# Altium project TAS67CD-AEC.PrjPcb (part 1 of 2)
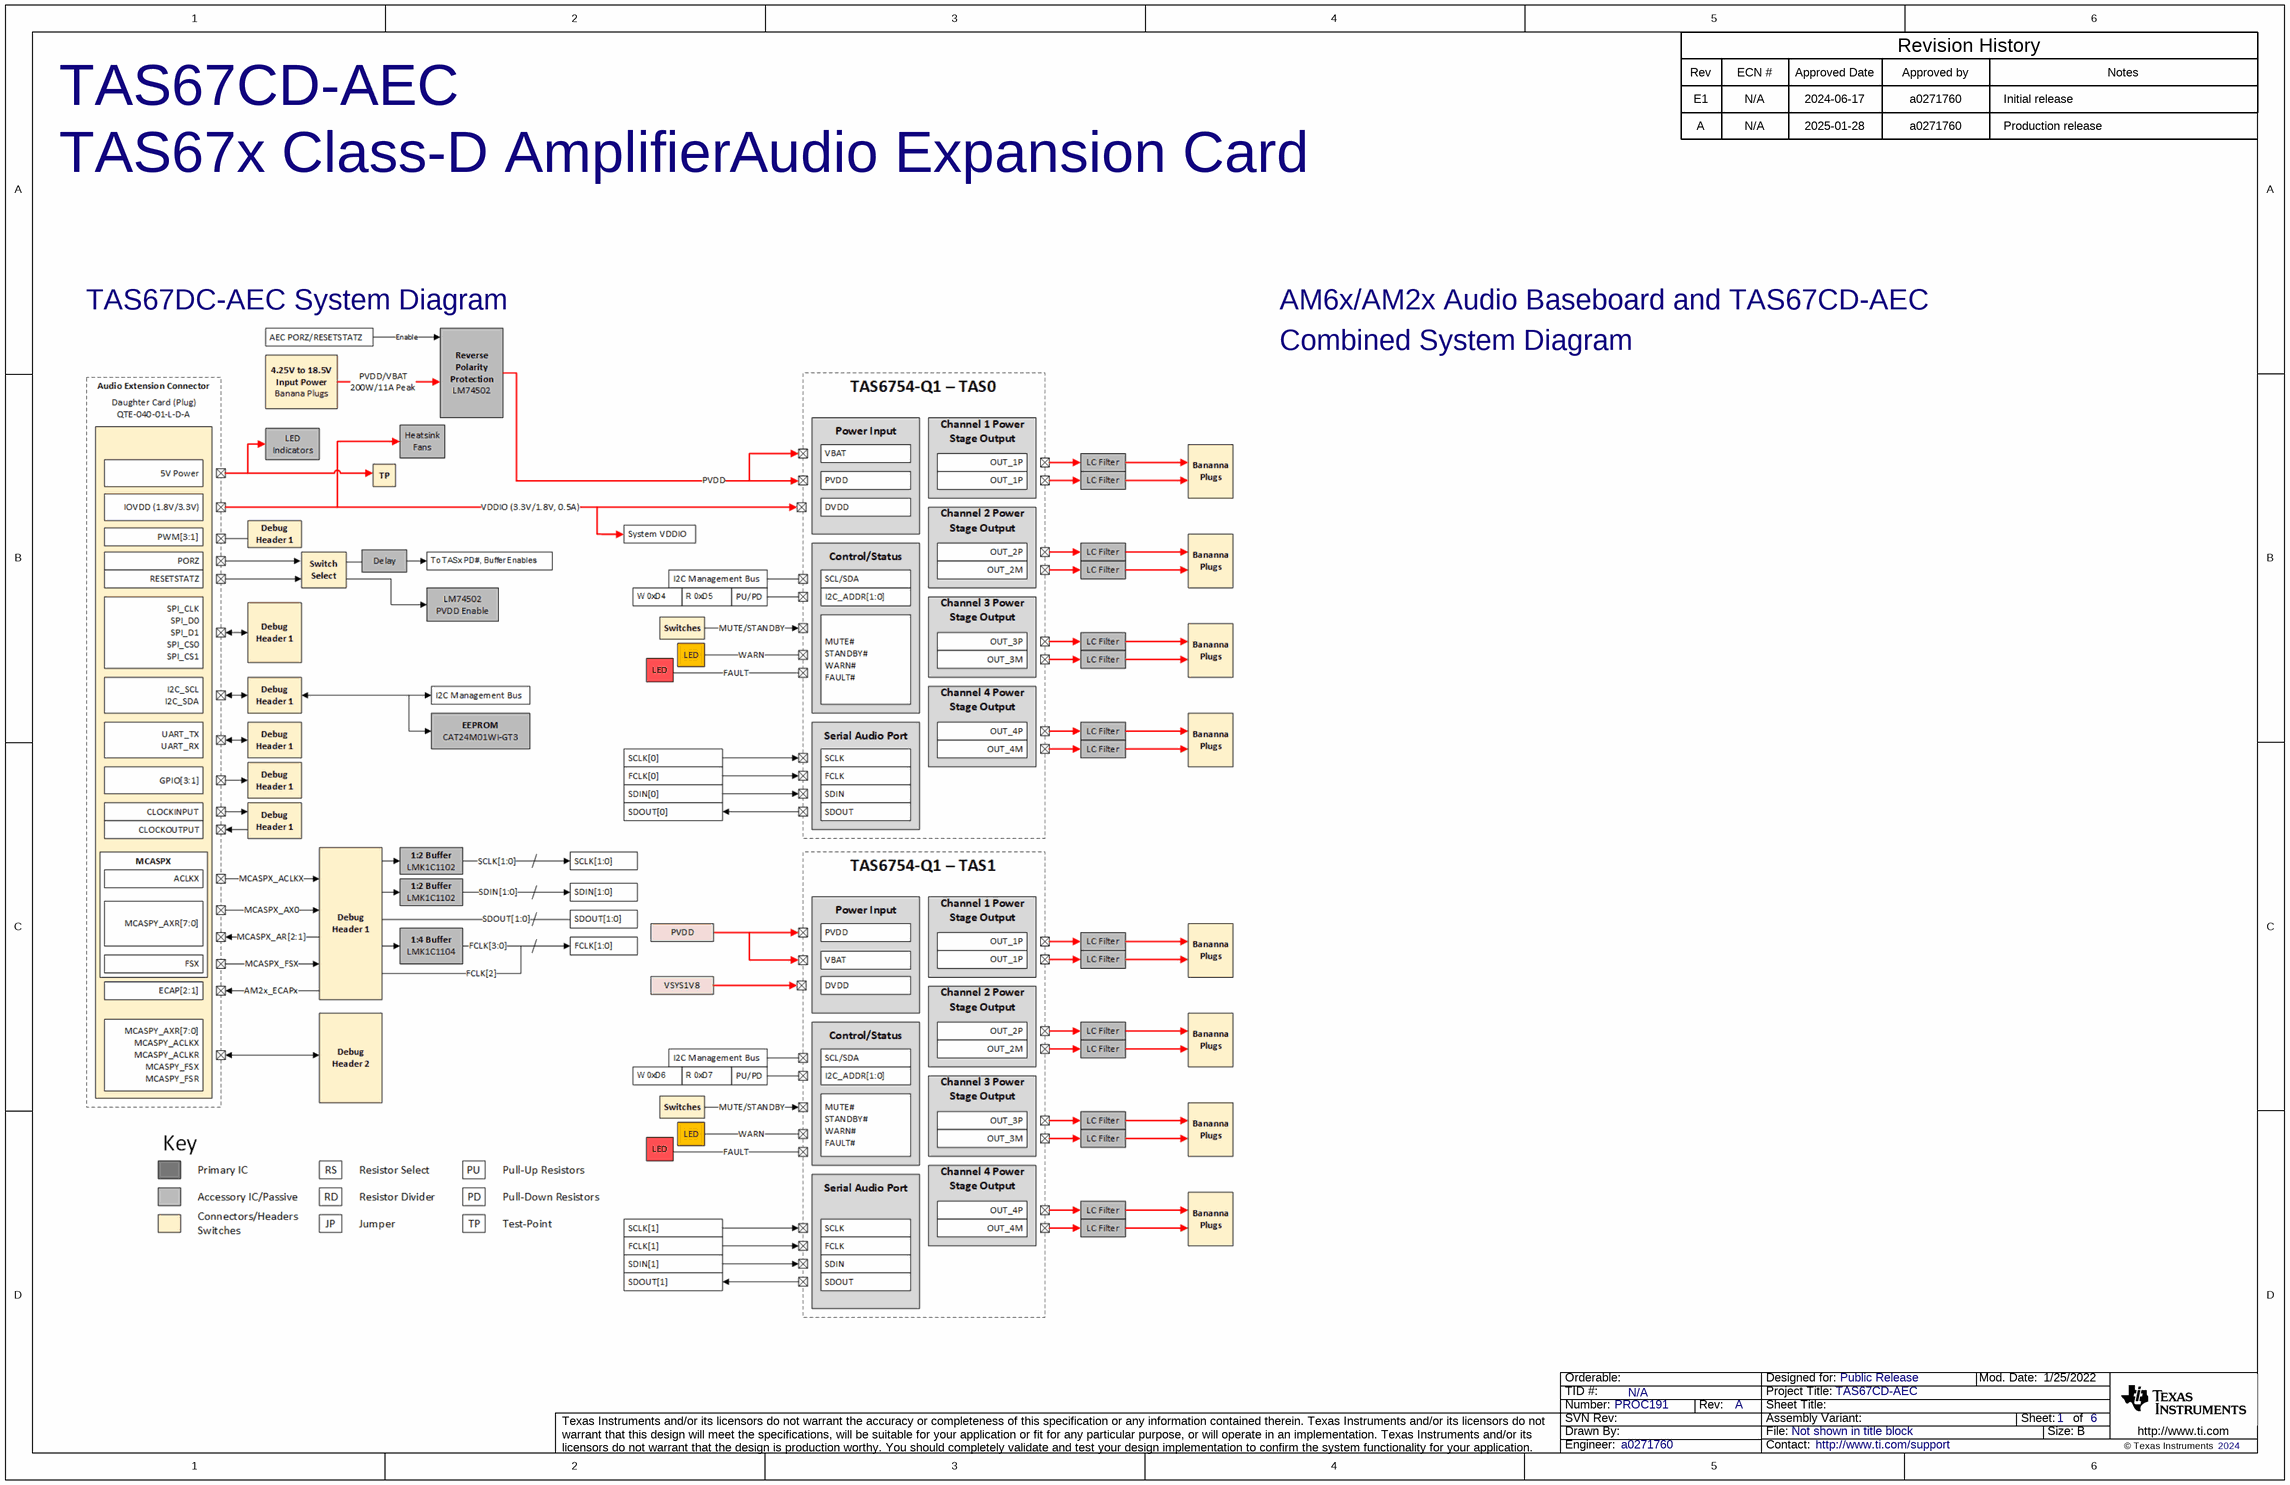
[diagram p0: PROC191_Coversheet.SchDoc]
CopyrightYear: 2024; PCB_Layout: a0271760; PCB_Rev: A; PRJ_Customer: Public Release; PRJ_Engineer: a0271760; PRJ_Number: PROC191; PRJ_Title: TAS67CD-AEC; SCH_Rev: A; TechSupport: http://www.ti.com/support; TID: N/A
6 sheets, 310 parts. Net scope: global (net labels, ports and power ports of the same name join across sheets).
Board file: PROC191A.PcbDoc
Sheets:
  PROC191_Coversheet.SchDoc
  PROC191_Power.SchDoc
  PROC191_ExpansionConnector.SchDoc
  PROC191_TAS0.SchDoc
  PROC191_TAS1.SchDoc
  PROC191_Hardware.SchDoc

## Sheet PROC191_Coversheet.SchDoc
size 431 x 279 mm; Date: Not shown in title block; ApprovedBy: Not shown in title block; CheckedBy: Not shown in title block; Author: Not shown in title block; CompanyName: Not shown in title block; Engineer: Not shown in title block; Organization: Not shown in title block; Address1: Not shown in title block; Address2: Not shown in title block; Address3: Not shown in title block; Address4: Not shown in title block; DocumentNumber: 1; Revision: Use project parameter SCH_Rev; SheetNumber: 1; SheetTotal: 6; PageSetup: Record=PageOptions¦CenterHorizontal=True¦CenterVertical=True¦PrintScale=1.00¦XCorrection=1.00¦YCorrection=1.00¦PrintKind=0¦BorderSize=5000000¦LeftOffset=0¦BottomOffset=0¦Orientation=2¦PaperLength=1000¦PaperWidth=1000¦Scale=100¦PaperSource=15¦PrintQuality=600¦MediaType=1¦DitherType=10¦PaperKind=Letter¦PrintScaleMode=1

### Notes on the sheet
- TAS67CD-AEC
- Rev
- E1
- ECN #
- N/A
- Approved Date
- 2024-06-17
- Approved by
- a0271760
- Revision History
- Initial release
- Notes
- TAS67x Class-D Amplifier
- Audio Expansion Card
- A
- 2025-01-28
- Production release
- TAS67DC-AEC System Diagram
- AM6x/AM2x Audio Baseboard and TAS67CD-AEC
- Combined System Diagram

## Sheet PROC191_Power.SchDoc
size 431 x 279 mm; Date: Not shown in title block; ApprovedBy: Not shown in title block; CheckedBy: Not shown in title block; Author: Not shown in title block; CompanyName: Not shown in title block; Engineer: Not shown in title block; Organization: Not shown in title block; Address1: Not shown in title block; Address2: Not shown in title block; Address3: Not shown in title block; Address4: Not shown in title block; DocumentNumber: 3; Revision: Use project parameter SCH_Rev; SheetNumber: 2; SheetTotal: 6; PageSetup: Record=PageOptions¦CenterHorizontal=True¦CenterVertical=True¦PrintScale=1.00¦XCorrection=1.00¦YCorrection=1.00¦PrintKind=0¦BorderSize=5000000¦LeftOffset=0¦BottomOffset=0¦Orientation=2¦PaperLength=1000¦PaperWidth=1000¦Scale=100¦PaperSource=15¦PrintQuality=600¦MediaType=1¦DitherType=10¦PaperKind=Letter¦PrintScaleMode=1
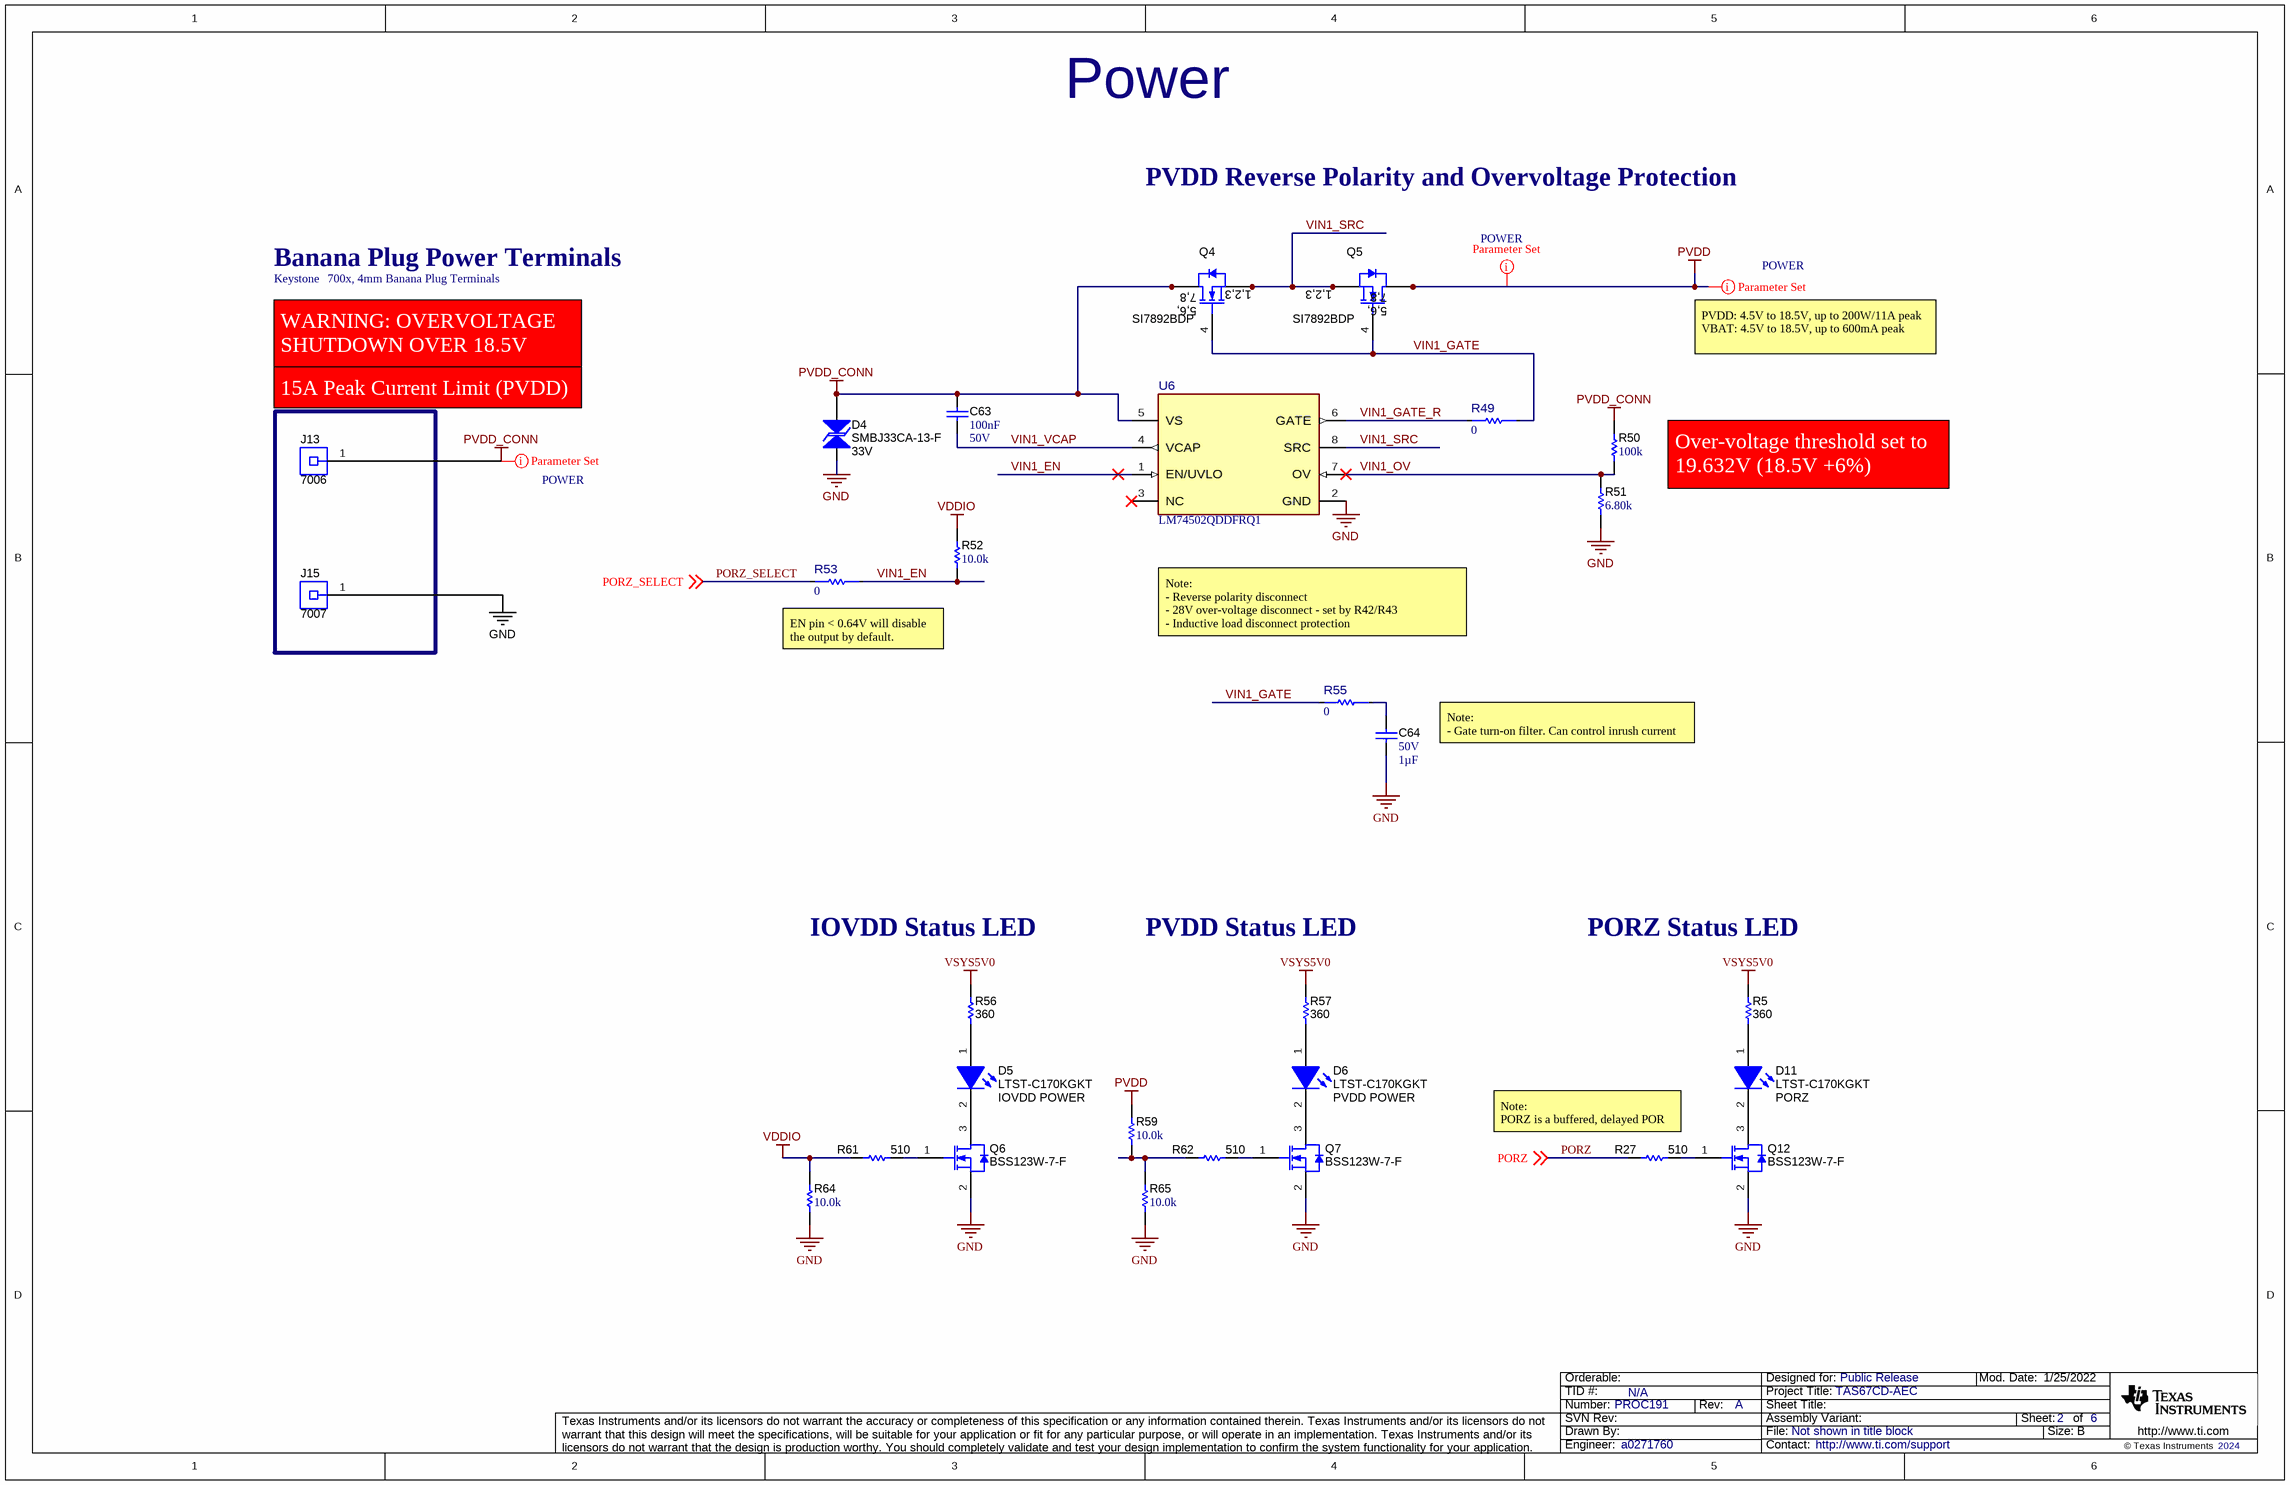
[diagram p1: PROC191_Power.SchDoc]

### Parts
C63  Cap_F: 100nF  VDC_V: 50V  [0603]  (hidden comment: GCM188R71H104KA57D)
C64  VDC_V: 50V  ValueDisplayed: 1µF  [0603]  (hidden comment: CGA3E3X5R1H105M080AB)
D4  SMBJ33CA-13-F  value 33V  [SMB-Bi]
D5  LTST-C170KGKT  value IOVDD POWER  [LTST-C170KGKT_Green]
D6  LTST-C170KGKT  value PVDD POWER  [LTST-C170KGKT_Green]
D11  LTST-C170KGKT  value PORZ  [LTST-C170KGKT_Green]
J13  7006  Manufacturer: Keystone  [Keystone_7006]
J15  7007  [Keystone_7007]
Q4  SI7892BDP  [PowerPAK_SO-8]
Q5  SI7892BDP  [PowerPAK_SO-8]
Q6  BSS123W-7-F  [SOT-323]
Q7  BSS123W-7-F  [SOT-323]
Q12  BSS123W-7-F  [SOT-323]
R5  ValueDisplayed: 360  [0402]  (hidden comment: ERJ-2GEJ361X)
R27  ValueDisplayed: 510  [0402]  (hidden comment: ERJ-2GEJ511X)
R49  Res_ohm: 0  [FP-ERJ-3GEY0R00V_0603-IPC_B]  (hidden comment: ERJ-3GEY0R00V)
R50  ValueDisplayed: 100k  [0603]  (hidden comment: RC0603FR-07100KL)
R51  ValueDisplayed: 6.80k  [0603]  (hidden comment: RC0603FR-076K8L)
R52  ValueDisplayed: 10.0k  [0603]  (hidden comment: RC0603FR-0710KL)
R53  Res_ohm: 0  [FP-ERJ-3GEY0R00V_0603-IPC_B]  (hidden comment: ERJ-3GEY0R00V)
R55  Res_ohm: 0  [FP-ERJ-3GEY0R00V_0603-IPC_B]  (hidden comment: ERJ-3GEY0R00V)
R56  ValueDisplayed: 360  [0402]  (hidden comment: ERJ-2GEJ361X)
R57  ValueDisplayed: 360  [0402]  (hidden comment: ERJ-2GEJ361X)
R59  ValueDisplayed: 10.0k  [0402]  (hidden comment: ERJ-2RKF1002X)
R61  ValueDisplayed: 510  [0402]  (hidden comment: ERJ-2GEJ511X)
R62  ValueDisplayed: 510  [0402]  (hidden comment: ERJ-2GEJ511X)
R64  ValueDisplayed: 10.0k  [0402]  (hidden comment: ERJ-2RKF1002X)
R65  ValueDisplayed: 10.0k  [0402]  (hidden comment: ERJ-2RKF1002X)
U6  PartNumber: LM74502QDDFRQ1  [DDF0008A-MFG]  (hidden comment: PartNumber)

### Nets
GND: C64.2 D4.1 J15.1 Q6.2(S) Q7.2(S) Q12.2(S) R51.1 R64.2 R65.2 U6.2(GND)
PVDD: Q5.5(D) Q5.6(D) Q5.7(D) Q5.8(D) Q5.9(D) R59.1
PVDD_CONN: C63.1 D4.2 J13.1 Q4.5(D) Q4.6(D) Q4.7(D) Q4.8(D) Q4.9(D) R50.2 U6.5(VS)
VDDIO: R52.2 R61.1 R64.1
VSYS5V0: R5.2 R56.2 R57.2
PORZ: R27.1 ; off-sheet PORZ
PORZ_SELECT: R53.2 ; off-sheet PORZ_SELECT
VIN1_EN: R52.1 R53.1 U6.1(EN/UVLO)
VIN1_GATE: Q4.4(G) Q5.4(G) R49.1 R55.2
VIN1_GATE_R: R49.2 U6.6(GATE)
VIN1_OV: R50.1 R51.2 U6.7(OV)
VIN1_SRC: Q4.1(S) Q4.2(S) Q4.3(S) Q5.1(S) Q5.2(S) Q5.3(S) U6.8(SRC)
VIN1_VCAP: C63.2 U6.4(VCAP)
NetC64_1: C64.1 R55.1
NetD5_1: D5.1(A) R56.1
NetD5_2: D5.2(K) Q6.3(D)
NetD6_1: D6.1(A) R57.1
NetD6_2: D6.2(K) Q7.3(D)
NetD11_1: D11.1(A) R5.1
NetD11_2: D11.2(K) Q12.3(D)
NetQ6_1: Q6.1(G) R61.2
NetQ7_1: Q7.1(G) R62.2
NetQ12_1: Q12.1(G) R27.2
NetR59_2: R59.2 R62.1 R65.1

Not connected (* = marked no-connect by the designer): U6 3(NC)*

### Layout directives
net class POWER: PVDD, PVDD_CONN

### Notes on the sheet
- Power
- PVDD Reverse Polarity and Overvoltage Protection
- Banana Plug Power Terminals
- 700x, 4mm Banana Plug Terminals
- WARNING: OVERVOLTAGE SHUTDOWN OVER 18.5V INPUT
- PVDD: 4.5V to 18.5V, up to 200W/11A peak
  VBAT: 4.5V to 18.5V, up to 600mA peak
- 15A Peak Current Limit (PVDD)
- Over-voltage threshold set to 19.632V (18.5V +6%)
- Note:
  - Reverse polarity disconnect
  - 28V over-voltage disconnect - set by R42/R43
  - Inductive load disconnect protection
- EN pin < 0.64V will disable the output by default.
- Note:
  - Gate turn-on filter. Can control inrush current
- IOVDD Status LED
- PVDD Status LED
- PORZ Status LED
- Note:
  PORZ is a buffered, delayed POR signal

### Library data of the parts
C63 = CMP-0007144-4: CAP, CERM, 0.1 uF, 50 V, +/- 10%, X7R, 0603; Manufacturer: MuRata; TaMin_C: -55°C; ESR_ohm: 20m; Polarized: N; SizeAreaWB_mm2: 4.68; Value1: 0.02 ohm; U/M: EA; Value: 0.1uF; TaMax_C: 125°C; SizeZ_mm: 1; SizeX_mm: 1.6; SizeY_mm: 0.8; SizeArea_mm2: 1.28; IRMS_A: 1.84A; AEC Category: Q200
C64 = CMP-0083707-1: CAP, CERM, 1 µF, 50 V,+/- 20%, X5R, AEC-Q200 Grade 3, 0603; Manufacturer: TDK; SizeAreaWB_mm2: 4.68; SizeArea_mm2: 1.28; AEC Qualified: Y; AEC Category: Q200; Value: 1uF; TaMax_C: 85°C; SizeZ_mm: 1; AEC Grade: 3; Polarized: N; TaMin_C: -55°C; SizeY_mm: 0.8; U/M: EA; SizeX_mm: 1.6
D4 = CMP-0005564-3: Diode, TVS, Bi, 33 V, SMB; Manufacturer: Diodes Inc.; SizeX_mm: 5.6; Ppk: 600W; SizeAreaWB_mm2: 44.156; SizeZ_mm: 2.6; SizeArea_mm2: 21.336; SizeY_mm: 3.81; AEC Category: Q101
D5 D6 D11 = CMP-0002888-2: LED, Green, SMD; Manufacturer: Lite-On; Value1: W; Vf_V: 2V; Type: AlInGaP; Io_A: 20mA
J13 = CMP-0055127-1: Binding Post, RED, TH; CNHeader: FALSE; Green_Lifecycle: Active; Green_REACh: Passed; CompType: Connector
J15 = CMP-0055128-1: Binding Post, BLACK, TH; Manufacturer: Keystone; CNHeader: FALSE; Green_Lifecycle: Active; Green_REACh: Passed; CompType: Connector
Q4 Q5 = CMP-0000665-1: MOSFET, N-CH, 30 V, 15 A, PowerPAK SO-8; Alternate Manufacturer: None; Manufacturer: Vishay-Siliconix; SizeZ_mm: 1.12; ChType: N; Value2: 27 nC; Value1: 0.005; VdsMax_V: 30V; SizeX_mm: 5.99; SizeAreaWB_mm2: 55.131; SizeY_mm: 4.9; Vgs_V: 20V; QgTyp_nC: 27; Value: 30V; Rdson45_ohm: 5.7m; SizeArea_mm2: 29.351; AEC Category: Q101; IdsMax_A: 15A; U/M: EA
Q6 Q7 Q12 = CMP-0000948-2: MOSFET, N-CH, 100 V, 0.17 A, SOT-323; Alternate Manufacturer: None; Manufacturer: Diodes Inc.; SizeZ_mm: 1.1; ChType: N; Value1: 1; VdsMax_V: 100V; SizeX_mm: 2.2; Vgs_V: 20V; Value: 100V; Rdson45_ohm: 10; SizeArea_mm2: 4.84; AEC Category: Q101; IdsMax_A: 170mA; SizeAreaWB_mm2: 10.24; U/M: EA
R5 R56 R57 = CMP-0078194-1: RES, 360, 5%, 0.1 W, AEC-Q200 Grade 0, 0402; Manufacturer: Panasonic; Value_Code: 360R; SizeArea_mm2: 0.5; AEC Qualified: Y; AEC Category: Q200; Value: 360; SizeZ_mm: 0.6; EIA_Code: E24; TempCo: 200 ppm/C; AEC Grade: 0; Power_W: 100mW; VDC_V: 50V; Value2: 0.1W; U/M: EA; SizeX_mm: 1
R27 R61 R62 = CMP-0078212-1: RES, 510, 5%, 0.1 W, AEC-Q200 Grade 0, 0402; Manufacturer: Panasonic; Value_Code: 510R; SizeArea_mm2: 0.5; AEC Qualified: Y; AEC Category: Q200; Value: 510; SizeZ_mm: 0.6; EIA_Code: E24; TempCo: 200 ppm/C; AEC Grade: 0; Power_W: 100mW; VDC_V: 50V; Value2: 0.1W; U/M: EA; SizeX_mm: 1
R49 R53 R55 = CMP-0089143-1: 0 Ohms Jumper 0.1W, 1/10W Chip Resistor 0603 (1608 Metric) Automotive AEC-Q200 Thick Film; Manufacturer: Panasonic; SizeZ_mm: 0.55mm; AEC Grade: Grade 0; VDC_V: 75V; TempCo: -100/+600ppm/°C; AEC Qualified: Yes; Power_W: 100mW; Tolerance_%: 5%
R50 = CMP-0022735-5: RES, 100 k, 1%, 0.1 W, 0603; Manufacturer: Yageo; Power_W: 100mW; TempCo: 100 ppm/C; Value: 100k; EIA_Code: E96; SizeX_mm: 1.6; SizeY_mm: 0.8; SizeZ_mm: 1; Value2: 0.1W; SizeArea_mm2: 1.28; AEC Qualified: N; VDC_V: 75V; AEC Category: Q200; SizeAreaWB_mm2: 4.68
R51 = CMP-0023253-5: RES, 6.80 k, 1%, 0.1 W, 0603; Manufacturer: Yageo; Power_W: 100mW; TempCo: 100 ppm/C; Value_Code: 6k80; Value: 6.80k; Res_ohm: 6.8k; SizeX_mm: 1.6; SizeY_mm: 0.8; SizeZ_mm: 1; Value2: 0.1W; SizeArea_mm2: 1.28; AEC Qualified: N; VDC_V: 75V; AEC Category: Q200; SizeAreaWB_mm2: 4.68
R52 = CMP-0022746-5: RES, 10.0 k, 1%, 0.1 W, 0603; Manufacturer: Yageo; Power_W: 100mW; TempCo: 100 ppm/C; Value_Code: 10k0; Value: 10.0k; EIA_Code: E96; Res_ohm: 10k; SizeX_mm: 1.6; SizeY_mm: 0.8; SizeZ_mm: 1; Value2: 0.1W; SizeArea_mm2: 1.28; AEC Qualified: N; VDC_V: 75V; AEC Category: Q200; SizeAreaWB_mm2: 4.68
R59 R64 R65 = CMP-0026658-1: RES, 10.0 k, 1%, 0.1 W, 0402; Manufacturer: Panasonic; Power_W: 100mW; TempCo: 100 ppm/C; Value_Code: 10k0; U/M: EA; Value: 10.0k; EIA_Code: E96; Res_ohm: 10k; SizeX_mm: 1; SizeY_mm: 0.5; SizeZ_mm: 0.6; Value2: 0.1W; VDC_V: 50V; AEC Category: Q200
U6 = CMP-0095578-1: Low IQ High Side Switch Controller With Reverse Polarity and Overvoltage Protection; Manufacturer: Texas Instruments; TJmax_C: +150°C; AEC Qualified: No; SizeZ_mm: 1.1mm; Nominal Supply Current: 45uA; Min Supply Voltage: 4V; Number Of Outputs: 1; Standoff Height: 0mm; Max Supply Voltage: 60V; TaMax_C: +125°C; TaMin_C: -40°C

## Sheet PROC191_ExpansionConnector.SchDoc
size 431 x 279 mm; Date: Not shown in title block; ApprovedBy: Not shown in title block; CheckedBy: Not shown in title block; Author: Not shown in title block; CompanyName: Not shown in title block; Engineer: Not shown in title block; Organization: Not shown in title block; Address1: Not shown in title block; Address2: Not shown in title block; Address3: Not shown in title block; Address4: Not shown in title block; DocumentNumber: 2; Revision: Use project parameter SCH_Rev; SheetNumber: 3; SheetTotal: 6; PageSetup: Record=PageOptions¦CenterHorizontal=True¦CenterVertical=True¦PrintScale=1.00¦XCorrection=1.00¦YCorrection=1.00¦PrintKind=0¦BorderSize=5000000¦LeftOffset=0¦BottomOffset=0¦Orientation=2¦PaperLength=1000¦PaperWidth=1000¦Scale=100¦PaperSource=15¦PrintQuality=600¦MediaType=1¦DitherType=10¦PaperKind=Letter¦PrintScaleMode=1
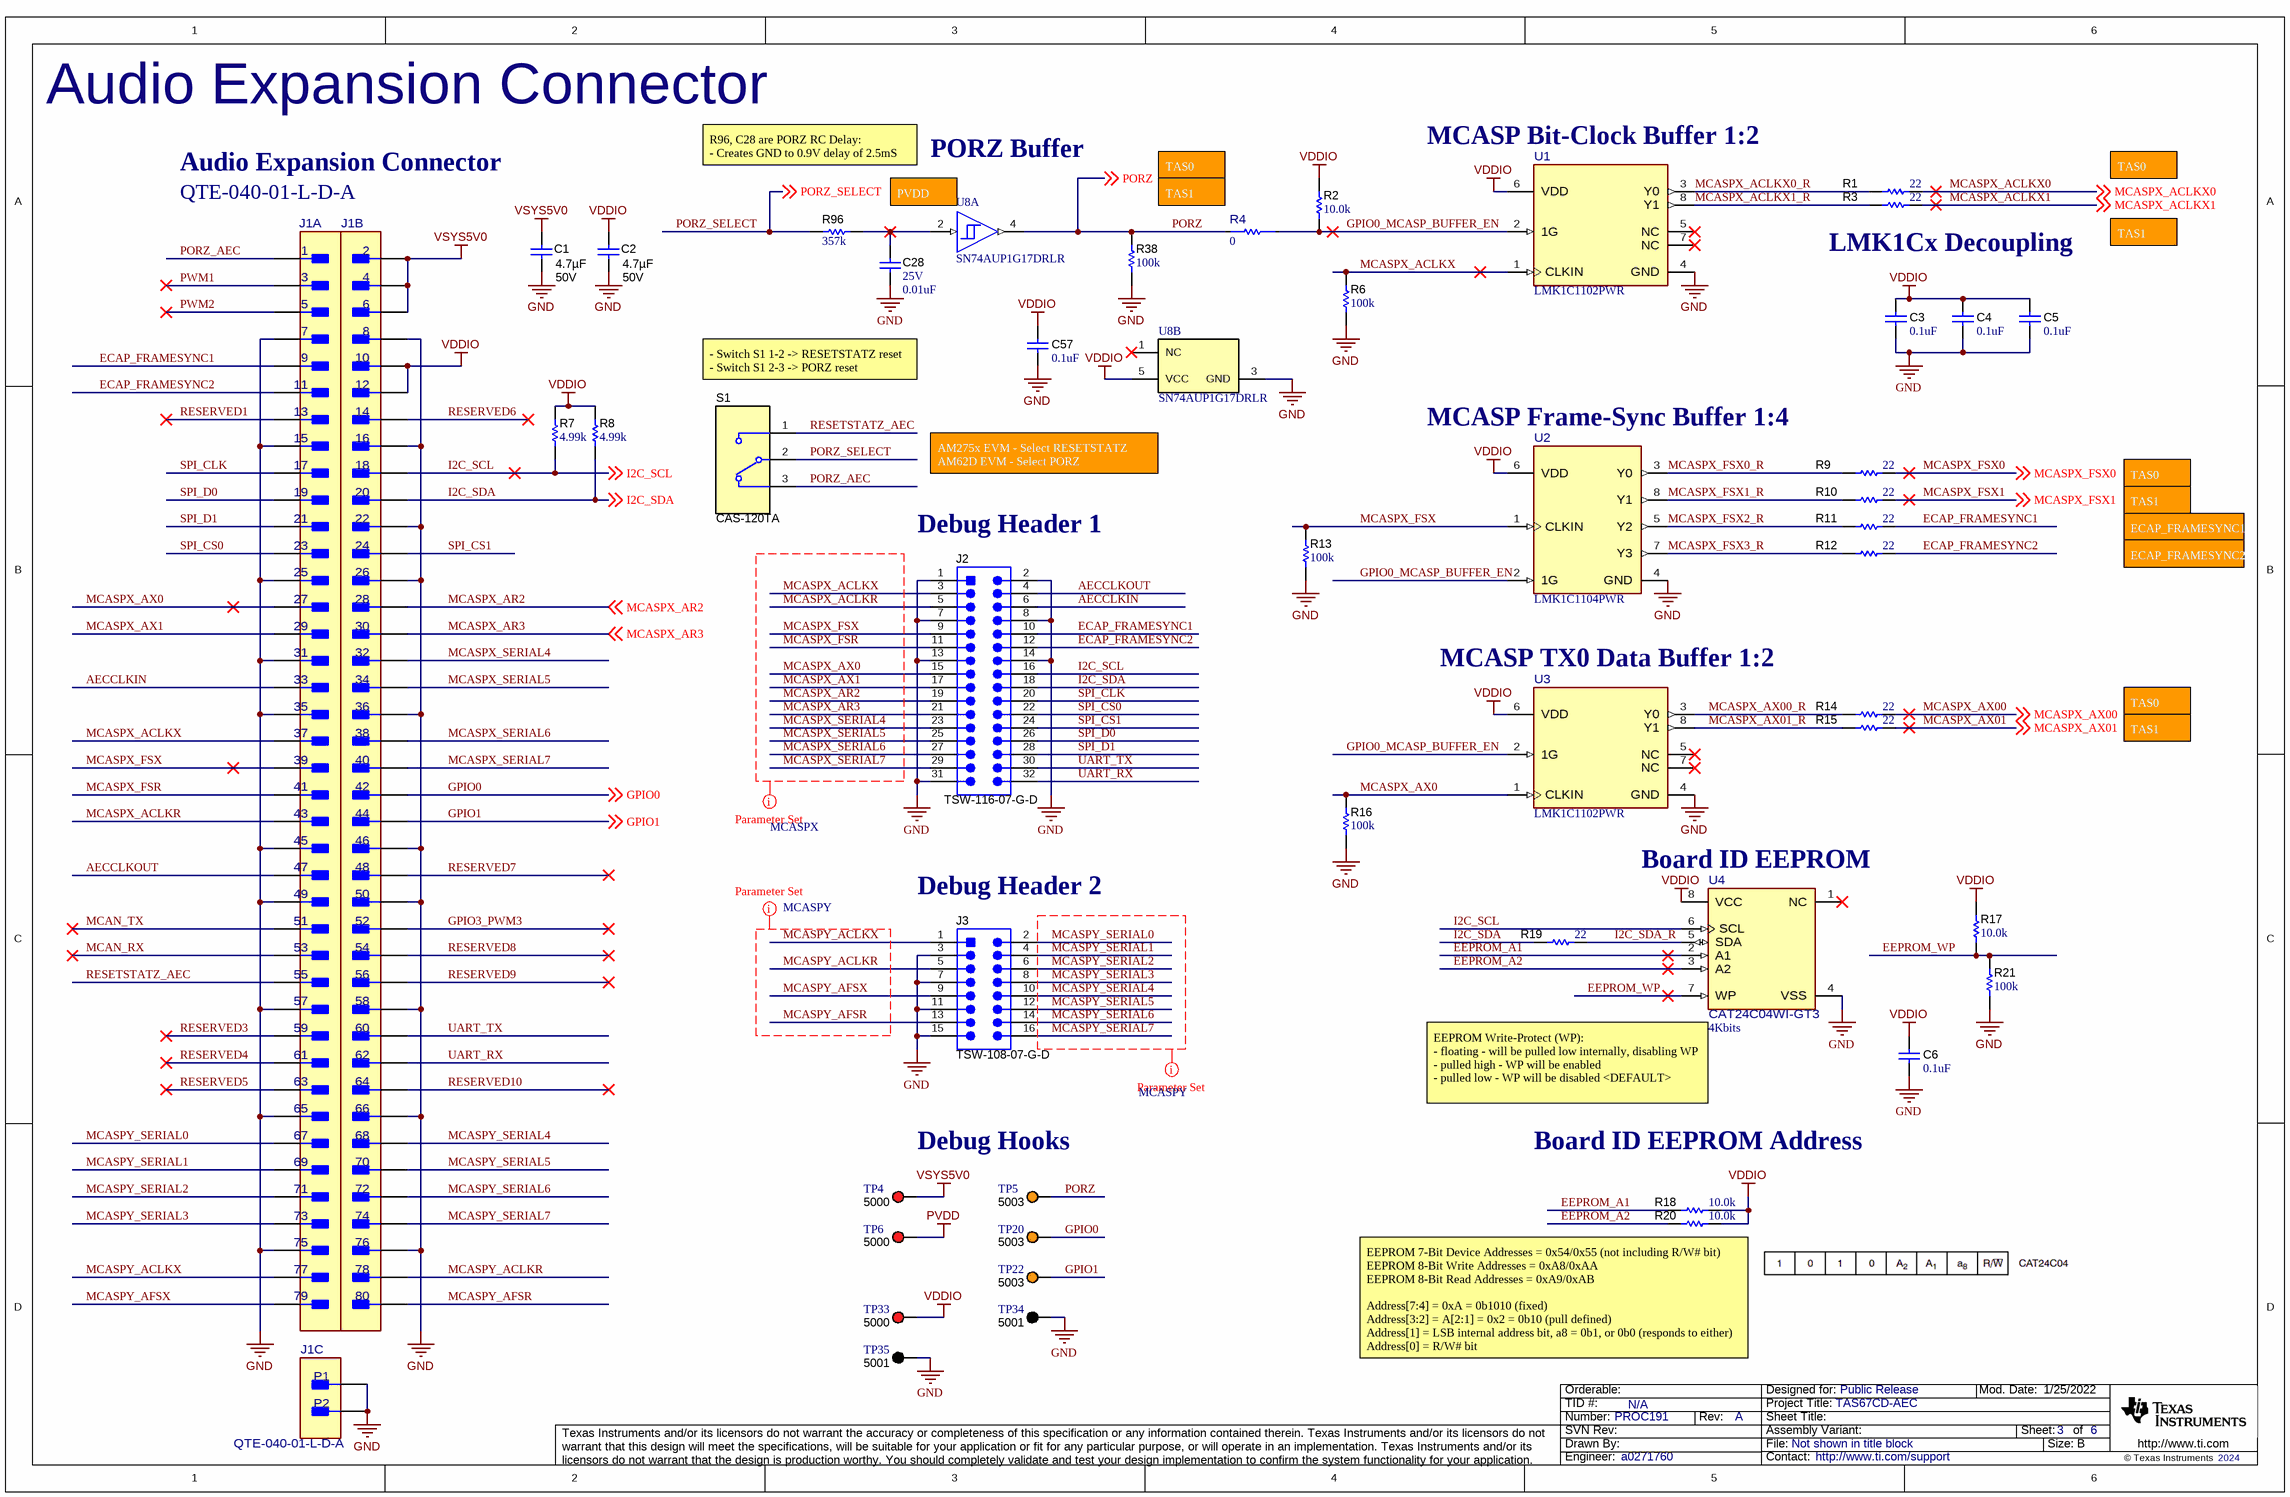
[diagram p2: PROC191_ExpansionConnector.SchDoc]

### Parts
C1  VDC_V: 50V  ValueDisplayed: 4.7µF  [1210_280]  (hidden comment: C1210C475K5RACAUTO)
C2  VDC_V: 50V  ValueDisplayed: 4.7µF  [1210_280]  (hidden comment: C1210C475K5RACAUTO)
C3  ValueDisplayed: 0.1uF  [0402]  (hidden comment: GRM155R71E104KE14D)
C4  ValueDisplayed: 0.1uF  [0402]  (hidden comment: GRM155R71E104KE14D)
C5  ValueDisplayed: 0.1uF  [0402]  (hidden comment: GRM155R71E104KE14D)
C6  ValueDisplayed: 0.1uF  [0402]  (hidden comment: GRM155R71E104KE14D)
C28  VDC_V: 25V  ValueDisplayed: 0.01uF  [0402]  (hidden comment: GRM155R71E103KA01D)
C57  ValueDisplayed: 0.1uF  [0402]  (hidden comment: GRM155R71E104KE14D)
J1  QTE-040-01-L-D-A  [FP-QTE-040-01-L-D-A_HDR80-MFG]  (parts A,B,C of 3)
J2  TSW-116-07-G-D  [TSW-116-07-G-D]
J3  TSW-108-07-G-D  [TSW-108-07-G-D]
R1  ValueDisplayed: 22  [0402]  (hidden comment: ERJ-2GEJ220X)
R2  ValueDisplayed: 10.0k  [0603]  (hidden comment: RC0603FR-0710KL)
R3  ValueDisplayed: 22  [0402]  (hidden comment: ERJ-2GEJ220X)
R4  Res_ohm: 0  [FP-ERJ-3GEY0R00V_0603-IPC_B]  (hidden comment: ERJ-3GEY0R00V)
R6  ValueDisplayed: 100k  [0603]  (hidden comment: RC0603FR-07100KL)
R7  ValueDisplayed: 4.99k  [0603]  (hidden comment: RC0603FR-074K99L)
R8  ValueDisplayed: 4.99k  [0603]  (hidden comment: RC0603FR-074K99L)
R9  ValueDisplayed: 22  [0402]  (hidden comment: ERJ-2GEJ220X)
R10  ValueDisplayed: 22  [0402]  (hidden comment: ERJ-2GEJ220X)
R11  ValueDisplayed: 22  [0402]  (hidden comment: ERJ-2GEJ220X)
R12  ValueDisplayed: 22  [0402]  (hidden comment: ERJ-2GEJ220X)
R13  ValueDisplayed: 100k  [0603]  (hidden comment: RC0603FR-07100KL)
R14  ValueDisplayed: 22  [0402]  (hidden comment: ERJ-2GEJ220X)
R15  ValueDisplayed: 22  [0402]  (hidden comment: ERJ-2GEJ220X)
R16  ValueDisplayed: 100k  [0603]  (hidden comment: RC0603FR-07100KL)
R17  ValueDisplayed: 10.0k  [0603]  (hidden comment: RC0603FR-0710KL)
R18  ValueDisplayed: 10.0k  [0603]  (hidden comment: RC0603FR-0710KL)
R19  ValueDisplayed: 22  [0402]  (hidden comment: ERJ-2GEJ220X)
R20  ValueDisplayed: 10.0k  [0603]  (hidden comment: RC0603FR-0710KL)
R21  ValueDisplayed: 100k  [0603]  (hidden comment: RC0603FR-07100KL)
R38  ValueDisplayed: 100k  [0603]  (hidden comment: RC0603FR-07100KL)
R96  ValueDisplayed: 357k  [0603]  (hidden comment: RC0603FR-07357KL)
S1  CAS-120TA  [SW_CAS-120TA]
TP4  5000  [Keystone5000]
TP5  5003  [Keystone5003]
TP6  5000  [Keystone5000]
TP20  5003  [Keystone5003]
TP22  5003  [Keystone5003]
TP33  5000  [Keystone5000]
TP34  5001  [Keystone5001]
TP35  5001  [Keystone5001]
U1  LMK1C1102PWR  [PW0008A-MFG]
U2  LMK1C1104PWR  [PW0008A-MFG]
U3  LMK1C1102PWR  [PW0008A-MFG]
U4  CAT24C04WI-GT3  Memory Size: 4Kbits  [FP-CAT24C04WI-GT3_SOIC8-IPC_C]
U8  SN74AUP1G17DRLR  [DRL0005A]  (parts A,B of 2)

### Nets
GND: C1.1 C2.1 C3.1 C4.1 C5.1 C6.1 C28.2 C57.1 J1.7 J1.8 J1.15 J1.16 J1.22 J1.25 J1.26 J1.31 J1.35 J1.36 J1.45 J1.46 J1.49 J1.50 J1.57 J1.58 J1.65 J1.66 J1.75 J1.76 J1.P1 J1.P2 J2.1 J2.2 J2.7 J2.8 J2.13 J2.14 J2.31 J3.3 J3.7 J3.11 J3.15 R6.1 R13.1 R16.1 R21.1 R38.1 TP34.1 TP35.1 U1.4(GND) U2.4(GND) U3.4(GND) U4.4(VSS) U8.3(GND)
PVDD: TP6.1
VDDIO: C2.2 C3.2 C4.2 C5.2 C6.2 C57.2 J1.10 J1.12 R2.1 R7.2 R8.2 R17.1 R18.1 R20.1 TP33.1 U1.6(VDD) U2.6(VDD) U3.6(VDD) U4.8(VCC) U8.5(VCC)
VSYS5V0: C1.2 J1.2 J1.4 J1.6 TP4.1
AECCLKIN: J1.33 J2.6
AECCLKOUT: J1.47 J2.4
ECAP_FRAMESYNC1: J1.9 J2.10 R11.2
ECAP_FRAMESYNC2: J1.11 J2.12 R12.2
EEPROM_A1: R18.2 U4.2(A1)
EEPROM_A2: R20.2 U4.3(A2)
EEPROM_WP: R17.2 R21.2 U4.7(WP)
GPIO0: J1.42 TP20.1 ; off-sheet GPIO0
GPIO0_MCASP_BUFFER_EN: R2.2 R4.1 U1.2(1G) U2.2(1G) U3.2(1G)
GPIO1: J1.44 TP22.1 ; off-sheet GPIO1
GPIO3_PWM3: J1.52
I2C_SCL: J1.18 J2.16 R7.1 U4.6(SCL) ; off-sheet I2C_SCL
I2C_SDA: J1.20 J2.18 R8.1 R19.1 ; off-sheet I2C_SDA
I2C_SDA_R: R19.2 U4.5(SDA)
MCAN_RX: J1.53
MCAN_TX: J1.51
MCASPX_ACLKR: J1.43 J2.5
MCASPX_ACLKX: J1.37 J2.3 R6.2 U1.1(CLKIN)
MCASPX_ACLKX0: R1.2 ; off-sheet MCASPX_ACLKX0
MCASPX_ACLKX0_R: R1.1 U1.3(Y0)
MCASPX_ACLKX1: R3.2 ; off-sheet MCASPX_ACLKX1
MCASPX_ACLKX1_R: R3.1 U1.8(Y1)
MCASPX_AR2: J1.28 J2.19 ; off-sheet MCASPX_AR2
MCASPX_AR3: J1.30 J2.21 ; off-sheet MCASPX_AR3
MCASPX_AX0: J1.27 J2.15 R16.2 U3.1(CLKIN)
MCASPX_AX00: R14.2 ; off-sheet MCASPX_AX00
MCASPX_AX00_R: R14.1 U3.3(Y0)
MCASPX_AX1: J1.29 J2.17
MCASPX_AX01: R15.2 ; off-sheet MCASPX_AX01
MCASPX_AX01_R: R15.1 U3.8(Y1)
MCASPX_FSR: J1.41 J2.11
MCASPX_FSX: J1.39 J2.9 R13.2 U2.1(CLKIN)
MCASPX_FSX0: R9.2 ; off-sheet MCASPX_FSX0
MCASPX_FSX0_R: R9.1 U2.3(Y0)
MCASPX_FSX1: R10.2 ; off-sheet MCASPX_FSX1
MCASPX_FSX1_R: R10.1 U2.8(Y1)
MCASPX_FSX2_R: R11.1 U2.5(Y2)
MCASPX_FSX3_R: R12.1 U2.7(Y3)
MCASPX_SERIAL4: J1.32 J2.23
MCASPX_SERIAL5: J1.34 J2.25
MCASPX_SERIAL6: J1.38 J2.27
MCASPX_SERIAL7: J1.40 J2.29
MCASPY_ACLKR: J1.78 J3.5
MCASPY_ACLKX: J1.77 J3.1
MCASPY_AFSR: J1.80 J3.13
MCASPY_AFSX: J1.79 J3.9
MCASPY_SERIAL0: J1.67 J3.2
MCASPY_SERIAL1: J1.69 J3.4
MCASPY_SERIAL2: J1.71 J3.6
MCASPY_SERIAL3: J1.73 J3.8
MCASPY_SERIAL4: J1.68 J3.10
MCASPY_SERIAL5: J1.70 J3.12
MCASPY_SERIAL6: J1.72 J3.14
MCASPY_SERIAL7: J1.74 J3.16
PORZ: R4.2 R38.2 TP5.1 U8.4(Y) ; off-sheet PORZ
PORZ_AEC: J1.1 S1.3
PORZ_SELECT: R96.1 S1.2 ; off-sheet PORZ_SELECT
PWM1: J1.3
PWM2: J1.5
RESERVED1: J1.13
RESERVED3: J1.59
RESERVED4: J1.61
RESERVED5: J1.63
RESERVED6: J1.14
RESERVED7: J1.48
RESERVED8: J1.54
RESERVED9: J1.56
RESERVED10: J1.64
RESETSTATZ_AEC: J1.55 S1.1
SPI_CLK: J1.17 J2.20
SPI_CS0: J1.23 J2.22
SPI_CS1: J1.24 J2.24
SPI_D0: J1.19 J2.26
SPI_D1: J1.21 J2.28
UART_RX: J1.62 J2.32
UART_TX: J1.60 J2.30
NetC28_1: C28.1 R96.2 U8.2(A)

Not connected (* = marked no-connect by the designer): U1 5(NC)* 7(NC)*; U3 5(NC)* 7(NC)*; U4 1(NC)*; U8 1(NC)*

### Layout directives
net class MCASPX: MCASPX_ACLKR, MCASPX_ACLKX, MCASPX_AR2, MCASPX_AR3, MCASPX_AX0, MCASPX_AX1, MCASPX_FSR, MCASPX_FSX, MCASPX_SERIAL4, MCASPX_SERIAL5, MCASPX_SERIAL6, MCASPX_SERIAL7
net class MCASPY: MCASPY_ACLKR, MCASPY_ACLKX, MCASPY_AFSR, MCASPY_AFSX, MCASPY_SERIAL0, MCASPY_SERIAL1, MCASPY_SERIAL2, MCASPY_SERIAL3, MCASPY_SERIAL4, MCASPY_SERIAL5, MCASPY_SERIAL6, MCASPY_SERIAL7

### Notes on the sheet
- Audio Expansion Connector
- R96, C28 are PORZ RC Delay:
  - Creates GND to 0.9V delay of 2.5mS
- PORZ Buffer
- TAS0
- (near U1) MCASP Bit-Clock Buffer 1:2
- (near U8) PVDD
- (near R4) TAS1
- TAS1
- LMK1Cx Decoupling
- - Switch S1 1-2 -> RESETSTATZ reset
  - Switch S1 2-3 -> PORZ reset
- (near U2) MCASP Frame-Sync Buffer 1:4
- AM275x EVM - Select RESETSTATZ
  AM62D EVM - Select PORZ
- (near J2) Debug Header 1
- ECAP_FRAMESYNC1
- ECAP_FRAMESYNC2
- MCASP TX0 Data Buffer 1:2
- (near J3) Debug Header 2
- (near U4) Board ID EEPROM
- (near U4) EEPROM Write-Protect (WP):
  - floating - will be pulled low internally, disabling WP
  - pulled high - WP will be enabled
  - pulled low - WP will be disabled <DEFAULT>
- Debug Hooks
- Board ID EEPROM Address
- (near R20) EEPROM 7-Bit Device Addresses = 0x54/0x55 (not including R/W# bit)
  EEPROM 8-Bit Write Addresses = 0xA8/0xAA
  EEPROM 8-Bit Read Addresses = 0xA9/0xAB
  Address[7:4] = 0xA = 0b1010 (fixed)
  Address[3:2] = A[2:1] = 0x2 = 0b10 (pull defined)
  Address[1] = LSB internal address bit, a8 = 0b1, or 0b0 (responds to either)
  Address[0] = R/W# bit

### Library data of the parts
C1 C2 = CMP-0079604-1: CAP, CERM, 4.7 µF, 50 V,+/- 10%, X7R, AEC-Q200 Grade 1, 1210; Manufacturer: Kemet; TaMin_C: -55°C; Polarized: N; SizeAreaWB_mm2: 14.7; U/M: EA; Value: 4.7uF; TaMax_C: 125°C; SizeZ_mm: 2.8; SizeX_mm: 3.2; SizeY_mm: 2.5; Cap_Case: 1210; SizeArea_mm2: 8; AEC Qualified: Y; AEC Grade: 1; AEC Category: Q200
C3-C6 C57 = CMP-0006659-2: CAP, CERM, 0.1 uF, 25 V, +/- 10%, X7R, 0402; Manufacturer: MuRata; TaMin_C: -55°C; Polarized: N; SizeAreaWB_mm2: 3; U/M: EA; Value: 0.1uF; TaMax_C: 125°C; SizeZ_mm: 0.6; SizeX_mm: 1; SizeY_mm: 0.5; Value2: 25V; Cap_F: 100nF; AEC Category: Q200; Value1: Unknown
C28 = CMP-0006658-2: CAP, CERM, 0.01 uF, 25 V, +/- 10%, X7R, 0402; Manufacturer: MuRata; TaMin_C: -55°C; Polarized: N; SizeAreaWB_mm2: 3; U/M: EA; Value: 0.01uF; TaMax_C: 125°C; SizeZ_mm: 0.6; SizeX_mm: 1; SizeY_mm: 0.5; Cap_F: 10nF; AEC Category: Q200; Value1: Unknown
J1 = CMP-0091968-1: 80 Position Connector Header, Outer Shroud Contacts Surface Mount Gold; Manufacturer: Samtec; SizeZ_mm: 4.347mm; AEC Qualified: No; Conn Gender: Male; Voltage_V: 225V; Row_Count: 2; ContactFinish: Gold,Nickel; Is Female: yes; Conn Orientation: Vertical; DUT-Pitch_mm: 0.8mm
J2 = CMP-0075429-1: Header, 100mil, 16x2, Gold, TH; Manufacturer: Samtec; Pitch_mm: 2.54; Cert_VDE: N; Gender: Male; Cert_CSA: Y; Voltage_V: 550V; Green_REACh: Passed; Current_A: 6.3A; CT: False; Green_Lifecycle: Active; Row_Count: 2; CNHeader: True
J3 = CMP-0075418-1: Header, 100mil, 8x2, Gold, TH; Manufacturer: Samtec; Pitch_mm: 2.54; Cert_VDE: N; Gender: Male; Cert_CSA: Y; Voltage_V: 550V; Green_REACh: Passed; Current_A: 6.3A; CT: False; Green_Lifecycle: Active; Row_Count: 2; CNHeader: True
R1 R3 R9-R12 R14 R15 R19 = CMP-0026997-2: RES, 22, 5%, 0.1 W, AEC-Q200 Grade 0, 0402; Manufacturer: Panasonic; Power_W: 100mW; TempCo: 200 ppm/C; Value_Code: 22R0; U/M: EA; Value: 22; EIA_Code: E24; SizeX_mm: 1; SizeY_mm: 0.5; SizeZ_mm: 0.6; Value2: 0.1W; AEC Qualified: Y; AEC Grade: 0; AEC Category: Q200
R2 R17 R18 R20 = CMP-0022746-5: as R52 on sheet PROC191_Power
R4 = CMP-0089143-1: as R49 on sheet PROC191_Power
R6 R13 R16 R21 R38 = CMP-0022735-5: as R50 on sheet PROC191_Power
R7 R8 = CMP-0023155-5: RES, 4.99 k, 1%, 0.1 W, 0603; Manufacturer: Yageo; Power_W: 100mW; TempCo: 100 ppm/C; Value_Code: 4k99; Value: 4.99k; EIA_Code: E96; SizeX_mm: 1.6; SizeY_mm: 0.8; SizeZ_mm: 1; Value2: 0.1W; SizeArea_mm2: 1.28; AEC Qualified: N; VDC_V: 75V; AEC Category: Q200; SizeAreaWB_mm2: 4.68
R96 = CMP-0023048-4: RES, 357 k, 1%, 0.1 W, 0603; Manufacturer: Yageo; Power_W: 100mW; TempCo: 100 ppm/C; Value: 357k; EIA_Code: E96; SizeX_mm: 1.6; SizeY_mm: 0.8; SizeZ_mm: 1; Value2: 0.1W; SizeArea_mm2: 1.28; AEC Qualified: N; VDC_V: 75V; AEC Category: Q200; SizeAreaWB_mm2: 4.68
S1 = CMP-0002139-2: Switch, Slide, SPDT  100mA, SMT; Manufacturer: Copal Electronics; CurrentRating_mA: 100A; SwitchFunction: On-On; VDC_V: 6V; PositionCount: 1
TP4 TP6 TP33 = CMP-0055137-2: Test Point, Miniature, Red, TH; Manufacturer: Keystone Electronics; Green_REACh: Passed; Green_Lifecycle: Active; ContactFinish: Silver; CNHeader: FALSE; CT: TRUE
TP5 TP20 TP22 = CMP-0055140-2: Test Point, Miniature, Orange, TH; Manufacturer: Keystone Electronics; Green_Lifecycle: Active; ContactFinish: Silver; CNHeader: FALSE; CT: TRUE; Green_REACh: Passed
TP34 TP35 = CMP-0055138-2: Test Point, Miniature, Black, TH; Manufacturer: Keystone Electronics; ContactFinish: Silver; CNHeader: FALSE; Green_Lifecycle: Active; Green_REACh: Passed; CT: TRUE
U1 U3 = CMP-0091149-1: Clock Clock Buffer IC 1:4 250MHz 8-TSSOP (0.173", 4.40mm Width); Manufacturer: Texas Instruments; Standoff Height: 0.05mm; SizeZ_mm: 1.2mm; Propagation Delay: 1.5ns; AEC Qualified: No; Number Of Outputs: 2; Nominal Supply Current: 25-33000uA; TaMin_C: -40°C; Min Supply Voltage: 1.71V; Max Supply Voltage: 3.465V; Number Of Elements: 1; TJmax_C: +150°C; TaMax_C: +125°C
U2 = CMP-0096980-1: 1.8-V, 2.5-V, and 3.3-V LVCMOS Clock Buffer Family; Manufacturer: Texas Instruments; Logic Function: Non-Inverting; TaMax_C: +125°C; TJmax_C: +150°C; Max Supply Voltage: 3.465V; Number Of Elements: 5; TaMin_C: -40°C; Nominal Supply Current: 25-33000uA; Number Of Outputs: 4; Number Of Inputs: 1; AEC Qualified: No; Min Supply Voltage: 1.71V; SizeZ_mm: 1.2mm; Standoff Height: 0.05mm; Propagation Delay: 1.5ns
U4 = CMP-0097697-1: EEPROM Memory IC 4Kbit I²C 400 kHz 900 ns 8-SOIC; Manufacturer: ON Semi; Standoff Height: 0.1mm; Nominal Supply Current: 1-2mA; SizeZ_mm: 1.75mm; AEC Qualified: No; Interface: I2C; Max Supply Voltage: 5.5V; Min Supply Voltage: 1.7V; Frequency_Fixed: 400kHz; Access Time: 0.9us
U8 = CMP-0051698-3: Low-Power Single Schmitt-Trigger Buffer, DRL0005A; Manufacturer: Texas Instruments; Logic: True; Bits(#): 1; Output Drive (IOL/IOH)(Max)(mA): 20/-20; Voltage(Nom)(V): 0.8,1.2,1.5,1.8,2.5,3.3; 3-State Output: No; ICC @ Nom Voltage(Max)(mA): 0.0009; Rating: Catalog; Schmitt Trigger: Yes; Technology Family: AUP; VCC(Min)(V): 0.8; Sub-Family: Non-Inverting Buffer/Driver; Output Type: CMOS; tpd @ Nom Voltage(Max)(ns): 35.1,18.1,12.9,11,7.9,6.7; VCC(Max)(V): 3.6; F @ Nom Voltage(Max)(Mhz): 100; AEC Category: Q200; AEC Qualified: N; CompType: IC; SizeX_mm: 1.6; SizeZ_mm: 0.6

## Sheet PROC191_TAS0.SchDoc
size 431 x 279 mm; Date: Not shown in title block; ApprovedBy: Not shown in title block; CheckedBy: Not shown in title block; Author: Not shown in title block; CompanyName: Not shown in title block; Engineer: Not shown in title block; Organization: Not shown in title block; Address1: Not shown in title block; Address2: Not shown in title block; Address3: Not shown in title block; Address4: Not shown in title block; DocumentNumber: 4; Revision: Use project parameter SCH_Rev; SheetNumber: 4; SheetTotal: 6; PageSetup: Record=PageOptions¦CenterHorizontal=True¦CenterVertical=True¦PrintScale=1.00¦XCorrection=1.00¦YCorrection=1.00¦PrintKind=0¦BorderSize=5000000¦LeftOffset=0¦BottomOffset=0¦Orientation=2¦PaperLength=1000¦PaperWidth=1000¦Scale=100¦PaperSource=15¦PrintQuality=600¦MediaType=1¦DitherType=10¦PaperKind=Letter¦PrintScaleMode=1
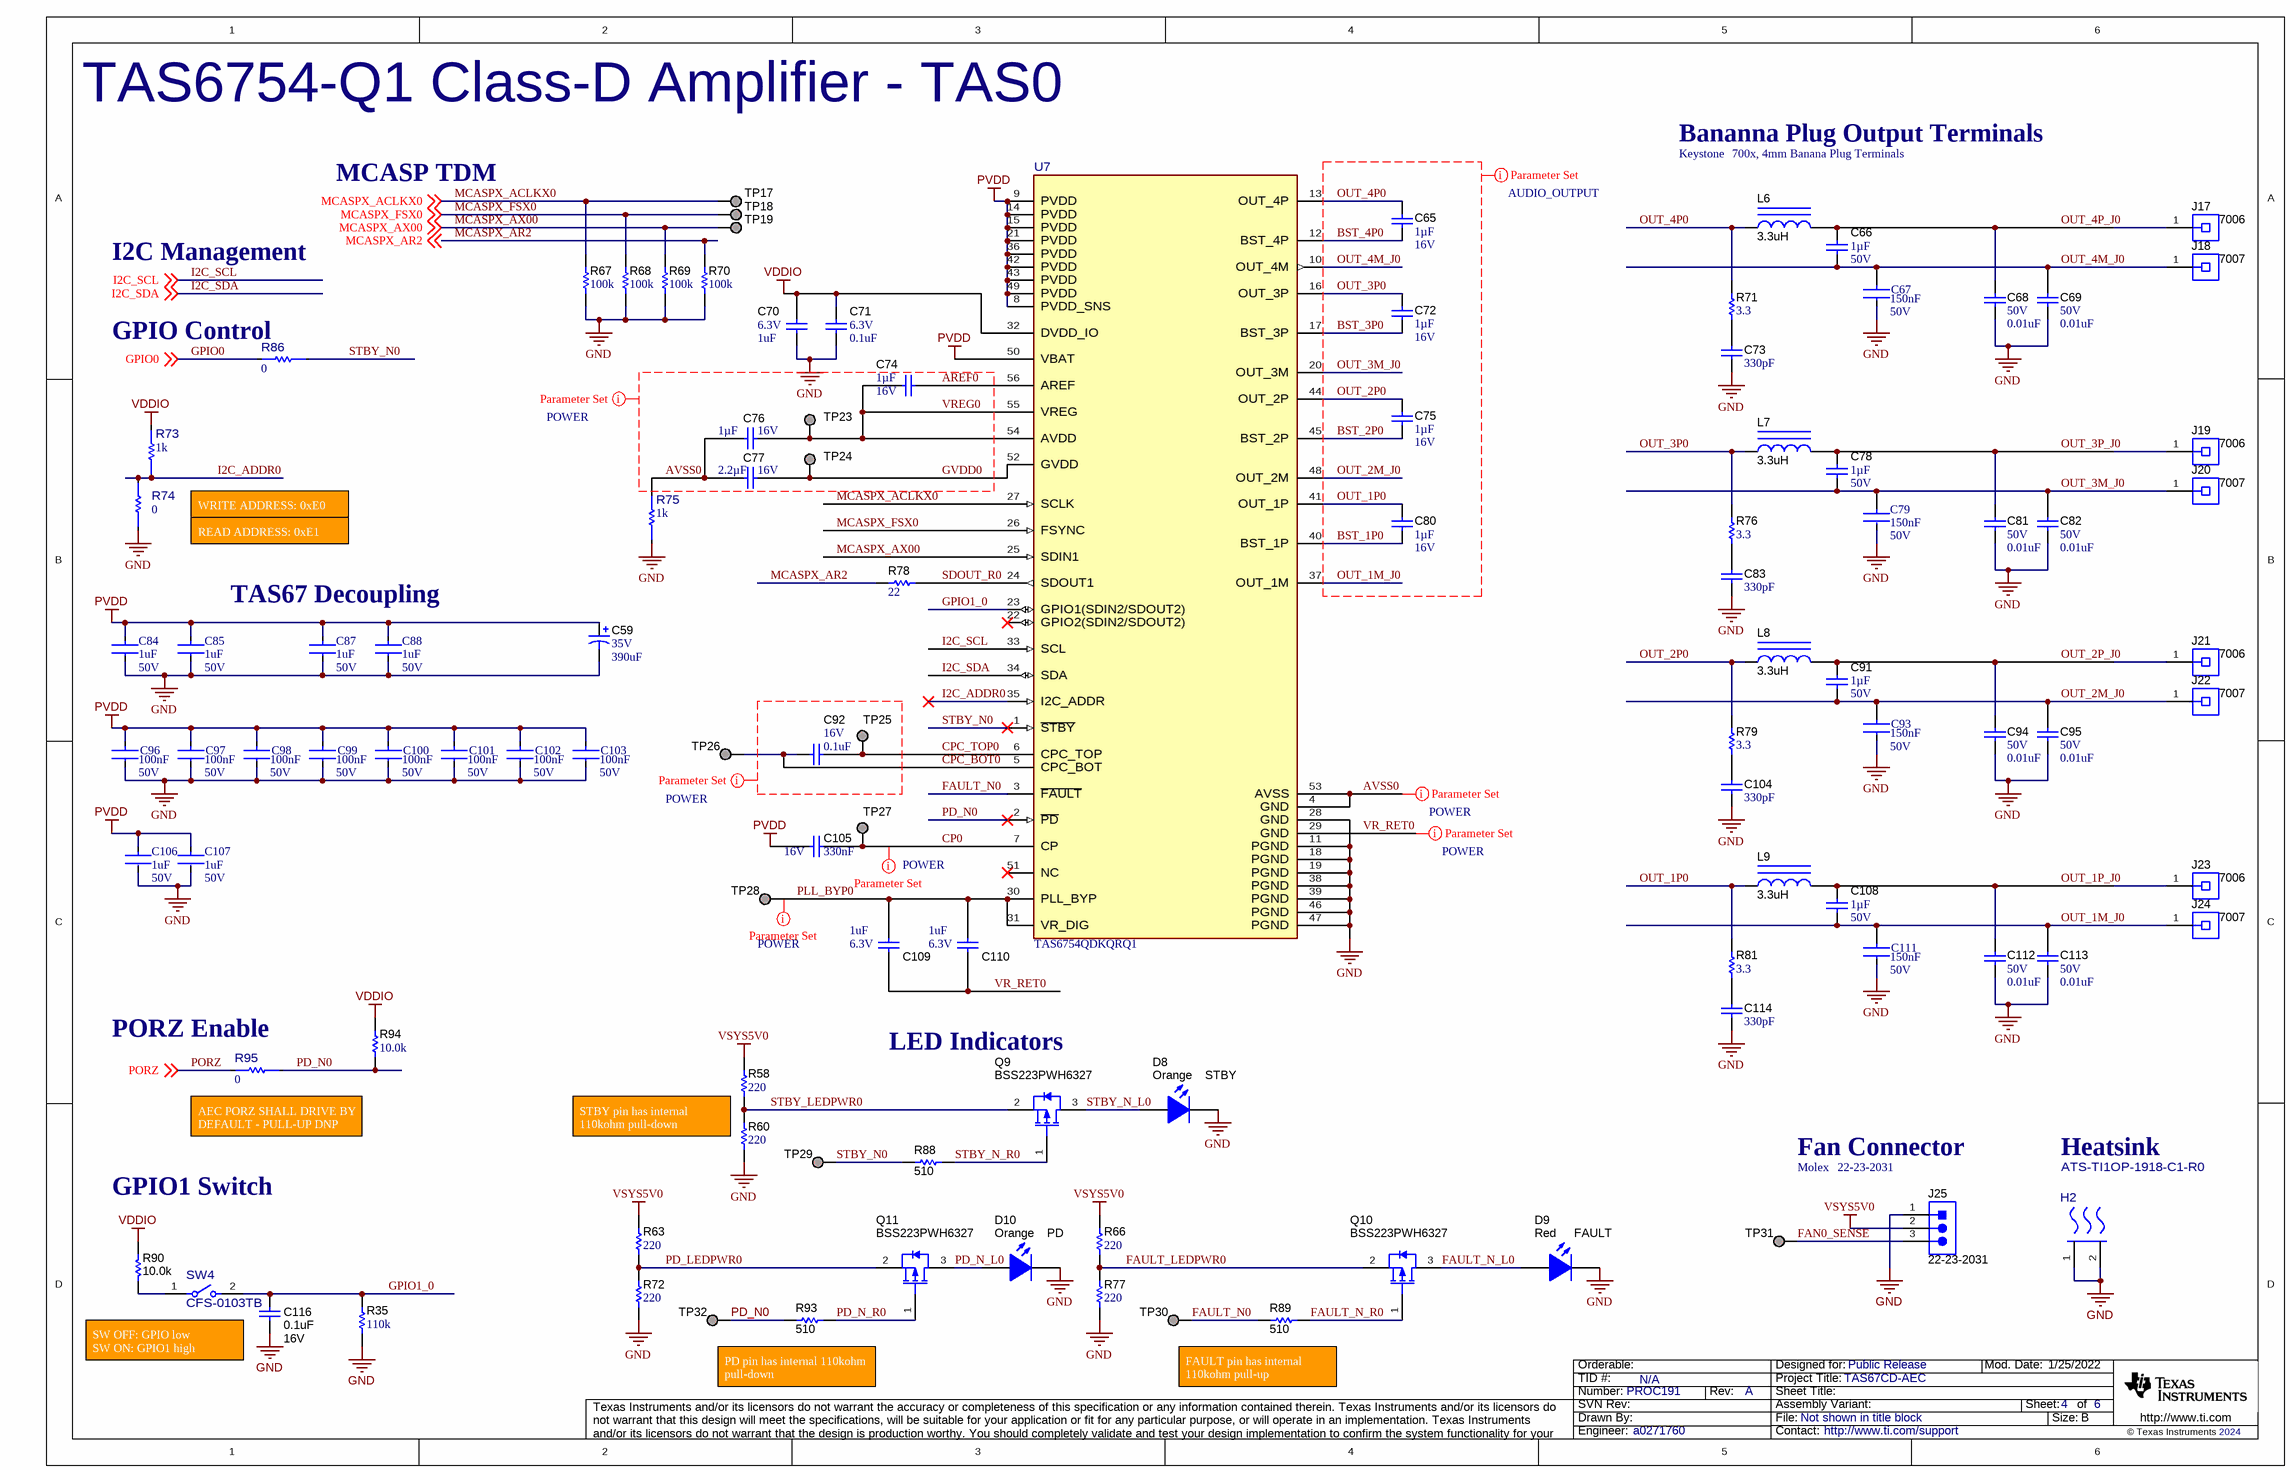
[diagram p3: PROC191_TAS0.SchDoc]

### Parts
C59  VDC_V: 35V  ValueDisplayed: 390uF  [SM_RADIAL_10BMM]  (hidden comment: UCL1V391MNL1GS)
C65  Cap_F: 1µF  VDC_V: 16V  [0603]  (hidden comment: GCM188R71C105KA64D)
C66  Cap_F: 1µF  VDC_V: 50V  [0805_HV]  (hidden comment: GCM21BR71H105KA03K)
C67  Voltage Rating: 50V  Capacitance: 150nF  [FP-GCM188-0_1-IPC_C]  (hidden comment: GCM188R71H154KA64D)
C68  VDC_V: 50V  ValueDisplayed: 0.01uF  [0603]  (hidden comment: GRM1885C1H103JA01D)
C69  VDC_V: 50V  ValueDisplayed: 0.01uF  [0603]  (hidden comment: GRM1885C1H103JA01D)
C70  VDC_V: 6.3V  ValueDisplayed: 1uF  [0402]  (hidden comment: GRM155R70J105KA12D)
C71  VDC_V: 6.3V  ValueDisplayed: 0.1uF  [0402]  (hidden comment: GRM155R70J104KA01D)
C72  Cap_F: 1µF  VDC_V: 16V  [0603]  (hidden comment: GCM188R71C105KA64D)
C73  ValueDisplayed: 330pF  [0402]  (hidden comment: GRM155R71H331KA01D)
C74  Cap_F: 1µF  VDC_V: 16V  [0603]  (hidden comment: GCM188R71C105MA64D)
C75  Cap_F: 1µF  VDC_V: 16V  [0603]  (hidden comment: GCM188R71C105KA64D)
C76  Cap_F: 1µF  VDC_V: 16V  [0603]  (hidden comment: GCM188R71C105MA64D)
C77  Cap_F: 2.2µF  VDC_V: 16V  [0603]  (hidden comment: EMK107BB7225KA-T)
C78  Cap_F: 1µF  VDC_V: 50V  [0805_HV]  (hidden comment: GCM21BR71H105KA03K)
C79  Voltage Rating: 50V  Capacitance: 150nF  [FP-GCM188-0_1-IPC_C]  (hidden comment: GCM188R71H154KA64D)
C80  Cap_F: 1µF  VDC_V: 16V  [0603]  (hidden comment: GCM188R71C105KA64D)
C81  VDC_V: 50V  ValueDisplayed: 0.01uF  [0603]  (hidden comment: GRM1885C1H103JA01D)
C82  VDC_V: 50V  ValueDisplayed: 0.01uF  [0603]  (hidden comment: GRM1885C1H103JA01D)
C83  ValueDisplayed: 330pF  [0402]  (hidden comment: GRM155R71H331KA01D)
C84  Voltage Rating: 50V  Capacitance: 1uF  [FP-GCJ21B-0_3-IPC_A]  (hidden comment: GCJ21BR71H105MA01L)
C85  Voltage Rating: 50V  Capacitance: 1uF  [FP-GCJ21B-0_3-IPC_A]  (hidden comment: GCJ21BR71H105MA01L)
C87  Voltage Rating: 50V  Capacitance: 1uF  [FP-GCJ21B-0_3-IPC_A]  (hidden comment: GCJ21BR71H105MA01L)
C88  Voltage Rating: 50V  Capacitance: 1uF  [FP-GCJ21B-0_3-IPC_A]  (hidden comment: GCJ21BR71H105MA01L)
C91  Cap_F: 1µF  VDC_V: 50V  [0805_HV]  (hidden comment: GCM21BR71H105KA03K)
C92  VDC_V: 16V  ValueDisplayed: 0.1uF  [0402]  (hidden comment: GCM155R71C104KA55D)
C93  Voltage Rating: 50V  Capacitance: 150nF  [FP-GCM188-0_1-IPC_C]  (hidden comment: GCM188R71H154KA64D)
C94  VDC_V: 50V  ValueDisplayed: 0.01uF  [0603]  (hidden comment: GRM1885C1H103JA01D)
C95  VDC_V: 50V  ValueDisplayed: 0.01uF  [0603]  (hidden comment: GRM1885C1H103JA01D)
C96  Voltage Rating (DC): 50V  Capacitance: 100nF  [FP-GCJ188-0_2-IPC_C]  (hidden comment: GCJ188R71H104KA12D)
C97  Voltage Rating (DC): 50V  Capacitance: 100nF  [FP-GCJ188-0_2-IPC_C]  (hidden comment: GCJ188R71H104KA12D)
C98  Voltage Rating (DC): 50V  Capacitance: 100nF  [FP-GCJ188-0_2-IPC_C]  (hidden comment: GCJ188R71H104KA12D)
C99  Voltage Rating (DC): 50V  Capacitance: 100nF  [FP-GCJ188-0_2-IPC_C]  (hidden comment: GCJ188R71H104KA12D)
C100  Voltage Rating (DC): 50V  Capacitance: 100nF  [FP-GCJ188-0_2-IPC_C]  (hidden comment: GCJ188R71H104KA12D)
C101  Voltage Rating (DC): 50V  Capacitance: 100nF  [FP-GCJ188-0_2-IPC_C]  (hidden comment: GCJ188R71H104KA12D)
C102  Voltage Rating (DC): 50V  Capacitance: 100nF  [FP-GCJ188-0_2-IPC_C]  (hidden comment: GCJ188R71H104KA12D)
C103  Voltage Rating (DC): 50V  Capacitance: 100nF  [FP-GCJ188-0_2-IPC_C]  (hidden comment: GCJ188R71H104KA12D)
C104  ValueDisplayed: 330pF  [0402]  (hidden comment: GRM155R71H331KA01D)
C105  Cap_F: 330nF  VDC_V: 16V  [0603]  (hidden comment: GRM188R71C334KA01D)
C106  Voltage Rating: 50V  Capacitance: 1uF  [FP-GCJ21B-0_3-IPC_A]  (hidden comment: GCJ21BR71H105MA01L)
C107  Voltage Rating: 50V  Capacitance: 1uF  [FP-GCJ21B-0_3-IPC_A]  (hidden comment: GCJ21BR71H105MA01L)
C108  Cap_F: 1µF  VDC_V: 50V  [0805_HV]  (hidden comment: GCM21BR71H105KA03K)
C109  VDC_V: 6.3V  ValueDisplayed: 1uF  [0402]  (hidden comment: GRM155R70J105KA12D)
C110  VDC_V: 6.3V  ValueDisplayed: 1uF  [0402]  (hidden comment: GRM155R70J105KA12D)
C111  Voltage Rating: 50V  Capacitance: 150nF  [FP-GCM188-0_1-IPC_C]  (hidden comment: GCM188R71H154KA64D)
C112  VDC_V: 50V  ValueDisplayed: 0.01uF  [0603]  (hidden comment: GRM1885C1H103JA01D)
C113  VDC_V: 50V  ValueDisplayed: 0.01uF  [0603]  (hidden comment: GRM1885C1H103JA01D)
C114  ValueDisplayed: 330pF  [0402]  (hidden comment: GRM155R71H331KA01D)
C116  VDC_V: 16V  ValueDisplayed: 0.1uF  [0402]  (hidden comment: C0402C104K4RACAUTO)
D8  STBY  value Orange  [LTST-C170KFKT_Orange]
D9  FAULT  value Red  [LED_LTST-C170_Red]
D10  PD  value Orange  [LTST-C170KFKT_Orange]
H2  ATS-TI1OP-1918-C1-R0  [FP-ATS-TI1OP-1918-C1-R0_HTSNK_41MM4_20MM0-MFG]
J17  7006  Manufacturer: Keystone  [Keystone_7006]
J18  7007  [Keystone_7007]
J19  7006  [Keystone_7006]
J20  7007  [Keystone_7007]
J21  7006  [Keystone_7006]
J22  7007  [Keystone_7007]
J23  7006  [Keystone_7006]
J24  7007  [Keystone_7007]
J25  22-23-2031  Manufacturer: Molex  [Molex_22-23-2031]
L6  ValueDisplayed: 3.3uH  [VCMT053T]  (hidden comment: VCMT053T-3R3MN5)
L7  ValueDisplayed: 3.3uH  [VCMT053T]  (hidden comment: VCMT053T-3R3MN5)
L8  ValueDisplayed: 3.3uH  [VCMT053T]  (hidden comment: VCMT053T-3R3MN5)
L9  ValueDisplayed: 3.3uH  [VCMT053T]  (hidden comment: VCMT053T-3R3MN5)
Q9  BSS223PWH6327  [SOT-323]
Q10  BSS223PWH6327  [SOT-323]
Q11  BSS223PWH6327  [SOT-323]
R35  ValueDisplayed: 110k  [0603]  (hidden comment: RC0603FR-07110KL)
R58  ValueDisplayed: 220  [0402]  (hidden comment: ERJ-2RKF2200X)
R60  ValueDisplayed: 220  [0402]  (hidden comment: ERJ-2RKF2200X)
R63  ValueDisplayed: 220  [0402]  (hidden comment: ERJ-2RKF2200X)
R66  ValueDisplayed: 220  [0402]  (hidden comment: ERJ-2RKF2200X)
R67  ValueDisplayed: 100k  [0402]  (hidden comment: RMCF0402FT100K)
R68  ValueDisplayed: 100k  [0402]  (hidden comment: RMCF0402FT100K)
R69  ValueDisplayed: 100k  [0402]  (hidden comment: RMCF0402FT100K)
R70  ValueDisplayed: 100k  [0402]  (hidden comment: RMCF0402FT100K)
R71  ValueDisplayed: 3.3  [0603]  (hidden comment: CRCW06033R30JNEA)
R72  ValueDisplayed: 220  [0402]  (hidden comment: ERJ-2RKF2200X)
R73  Res_ohm: 1k  [FP-ERJ-3GEYJ102V_0603-MFG]  (hidden comment: ERJ-3GEYJ102V)
R74  Res_ohm: 0  [FP-ERJ-3GEY0R00V_0603-MFG]  (hidden comment: ERJ-3GEY0R00V)
R75  Res_ohm: 1k  [FP-ERJ-3GEYJ102V_0603-MFG]  (hidden comment: ERJ-3GEYJ102V)
R76  ValueDisplayed: 3.3  [0603]  (hidden comment: CRCW06033R30JNEA)
R77  ValueDisplayed: 220  [0402]  (hidden comment: ERJ-2RKF2200X)
R78  ValueDisplayed: 22  [0402]  (hidden comment: ERJ-2GEJ220X)
R79  ValueDisplayed: 3.3  [0603]  (hidden comment: CRCW06033R30JNEA)
R81  ValueDisplayed: 3.3  [0603]  (hidden comment: CRCW06033R30JNEA)
R86  Res_ohm: 0  [FP-ERJ-3GEY0R00V_0603-IPC_B]  (hidden comment: ERJ-3GEY0R00V)
R88  ValueDisplayed: 510  [0402]  (hidden comment: ERJ-2GEJ511X)
R89  ValueDisplayed: 510  [0402]  (hidden comment: ERJ-2GEJ511X)
R90  ValueDisplayed: 10.0k  [0402]  (hidden comment: RMCF0402FT10K0)
R93  ValueDisplayed: 510  [0402]  (hidden comment: ERJ-2GEJ511X)
R94  ValueDisplayed: 10.0k  [0603]  (hidden comment: RC0603FR-0710KL)
R95  Res_ohm: 0  [FP-ERJ-3GEY0R00V_0603-IPC_B]  (hidden comment: ERJ-3GEY0R00V)
SW4  CFS-0103TB  [FP-CFS-0103TB_SMT_SW_6MM40_3MM95-MFG]
TP17  AVDD  [TP_SM_1MM]  (value not drawn)  (no BOM)
TP18  AVDD  [TP_SM_1MM]  (value not drawn)  (no BOM)
TP19  AVDD  [TP_SM_1MM]  (value not drawn)  (no BOM)
TP23  AVDD  [TP_SM_1MM]  (value not drawn)  (no BOM)
TP24  AVDD  [TP_SM_1MM]  (value not drawn)  (no BOM)
TP25  CPC_TOP  [TP_SM_1MM]  (value not drawn)  (no BOM)
TP26  CPC_BOT  [TP_SM_1MM]  (value not drawn)  (no BOM)
TP27  CP  [TP_SM_1MM]  (value not drawn)  (no BOM)
TP28  VR_DIG  [TP_SM_1MM]  (value not drawn)  (no BOM)
TP29  FAULT  [TP_SM_1MM]  (value not drawn)  (no BOM)
TP30  FAULT  [TP_SM_1MM]  (value not drawn)  (no BOM)
TP31  VR_DIG  [TP_SM_1MM]  (value not drawn)  (no BOM)
TP32  FAULT  [TP_SM_1MM]  (value not drawn)  (no BOM)
U7  TAS6754QDKQRQ1  [DKQ0056C-MFG]

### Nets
GND: C59.2(-) C67.2 C68.2 C69.2 C70.2 C71.2 C73.1 C79.2 C81.2 C82.2 C83.1 C84.2 C85.2 C87.2 C88.2 C93.2 C94.2 C95.2 C96.1 C97.1 C98.1 C99.1 C100.1 C101.1 C102.1 C103.1 C104.1 C106.2 C107.2 C111.2 C112.2 C113.2 C114.1 C116.2 D8.2(K) D9.2(K) D10.2(K) H2.1(MNT_1) H2.2(MNT_2) J25.1 R35.1 R60.2 R67.1 R68.1 R69.1 R70.1 R72.2 R74.1 R75.1 R77.2 U7.11(PGND) U7.18(PGND) U7.19(PGND) U7.28(GND) U7.38(PGND) U7.39(PGND) U7.46(PGND) U7.47(PGND)
PVDD: C59.1(+) C84.1 C85.1 C87.1 C88.1 C96.2 C97.2 C98.2 C99.2 C100.2 C101.2 C102.2 C103.2 C105.2 C106.1 C107.1 U7.8(PVDD_SNS) U7.9(PVDD) U7.14(PVDD) U7.15(PVDD) U7.21(PVDD) U7.36(PVDD) U7.42(PVDD) U7.43(PVDD) U7.49(PVDD) U7.50(VBAT)
VDDIO: C70.1 C71.1 R73.2 R90.2 R94.2 U7.32(DVDD_IO)
VSYS5V0: J25.2 R58.1 R63.1 R66.1
AREF0: C74.1 U7.56(AREF)
AVSS0: C76.2 C77.1 R75.2 U7.4(GND) U7.53(AVSS)
BST_1P0: C80.1 U7.40(BST_1P)
BST_2P0: C75.1 U7.45(BST_2P)
BST_3P0: C72.1 U7.17(BST_3P)
BST_4P0: C65.1 U7.12(BST_4P)
CP0: C105.1 TP27.1 U7.7(CP)
CPC_BOT0: C92.1 TP26.1 U7.5(CPC_BOT)
CPC_TOP0: C92.2 TP25.1 U7.6(CPC_TOP)
FAN0_SENSE: J25.3 TP31.1
FAULT_LEDPWR0: Q10.2(S) R66.2 R77.1
FAULT_N0: R89.2 TP30.1 U7.3(~{FAULT})
FAULT_N_L0: D9.1(A) Q10.3(D)
FAULT_N_R0: Q10.1(G) R89.1
GPIO0: R86.2 ; off-sheet GPIO0
GPIO1_0: C116.1 R35.2 SW4.2 U7.23(GPIO1(SDIN2/SDOUT2))
GVDD0: C77.2 TP24.1 U7.52(GVDD)
I2C_ADDR0: R73.1 R74.2 U7.35(I2C_ADDR)
I2C_SCL: U7.33(SCL) ; off-sheet I2C_SCL
I2C_SDA: U7.34(SDA) ; off-sheet I2C_SDA
MCASPX_ACLKX0: R67.2 TP17.1 U7.27(SCLK) ; off-sheet MCASPX_ACLKX0
MCASPX_AR2: R70.2 R78.1 ; off-sheet MCASPX_AR2
MCASPX_AX00: R69.2 TP19.1 U7.25(SDIN1) ; off-sheet MCASPX_AX00
MCASPX_FSX0: R68.2 TP18.1 U7.26(FSYNC) ; off-sheet MCASPX_FSX0
OUT_1M_J0: C108.2 C111.1 C113.1 J24.1 U7.37(OUT_1M)
OUT_1P0: C80.2 L9.1 R81.2 U7.41(OUT_1P)
OUT_1P_J0: C108.1 C112.1 J23.1 L9.2
OUT_2M_J0: C91.2 C93.1 C95.1 J22.1 U7.48(OUT_2M)
OUT_2P0: C75.2 L8.1 R79.2 U7.44(OUT_2P)
OUT_2P_J0: C91.1 C94.1 J21.1 L8.2
OUT_3M_J0: C78.2 C79.1 C82.1 J20.1 U7.20(OUT_3M)
OUT_3P0: C72.2 L7.1 R76.2 U7.16(OUT_3P)
OUT_3P_J0: C78.1 C81.1 J19.1 L7.2
OUT_4M_J0: C66.2 C67.1 C69.1 J18.1 U7.10(OUT_4M)
OUT_4P0: C65.2 L6.1 R71.2 U7.13(OUT_4P)
OUT_4P_J0: C66.1 C68.1 J17.1 L6.2
PD_LEDPWR0: Q11.2(S) R63.2 R72.1
PD_N0: R93.2 R94.1 R95.1 TP32.1 U7.2(~{PD})
PD_N_L0: D10.1(A) Q11.3(D)
PD_N_R0: Q11.1(G) R93.1
PLL_BYP0: C109.1 C110.1 TP28.1 U7.30(PLL_BYP) U7.31(VR_DIG)
PORZ: R95.2 ; off-sheet PORZ
SDOUT_R0: R78.2 U7.24(SDOUT1)
STBY_LEDPWR0: Q9.2(S) R58.2 R60.1
STBY_N0: R86.1 R88.2 TP29.1 U7.1(~{STBY})
STBY_N_L0: D8.1(A) Q9.3(D)
STBY_N_R0: Q9.1(G) R88.1
VR_RET0: C109.2 C110.2 U7.29(GND)
VREG0: C74.2 C76.1 TP23.1 U7.54(AVDD) U7.55(VREG)
NetC73_2: C73.2 R71.1
NetC83_2: C83.2 R76.1
NetC104_2: C104.2 R79.1
NetC114_2: C114.2 R81.1
NetR90_1: R90.1 SW4.1

Not connected (* = marked no-connect by the designer): U7 22(GPIO2(SDIN2/SDOUT2))* 51(NC)*

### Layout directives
net class AUDIO_OUTPUT: BST_1P0, BST_2P0, BST_3P0, BST_4P0, OUT_1M_J0, OUT_1P0, OUT_2M_J0, OUT_2P0, OUT_3M_J0, OUT_3P0, OUT_4M_J0, OUT_4P0
net class POWER: (no net found under the mark), AREF0, AVSS0, CP0, GVDD0, PLL_BYP0, VR_RET0, VREG0

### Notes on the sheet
- TAS6754-Q1 Class-D Amplifier - TAS0
- Bananna Plug Output Terminals
- 700x, 4mm Banana Plug Terminals
- MCASP TDM
- I2C Management
- (near R86) GPIO Control
- WRITE ADDRESS: 0xE0
- READ ADDRESS: 0xE1
- TAS67 Decoupling
- (near R95) PORZ Enable
- LED Indicators
- AEC PORZ SHALL DRIVE BY DEFAULT - PULL-UP DNP
- STBY pin has internal 110kohm pull-down
- Fan Connector
- Heatsink
- GPIO1 Switch
- SW OFF: GPIO low
  SW ON: GPIO1 high
- PD pin has internal 110kohm pull-down
- FAULT pin has internal 110kohm pull-up

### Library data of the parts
C59 = CMP-0011092-1: CAP, AL, 390 uF, 35 V, +/- 20%, 0.08 ohm, SMD; Manufacturer: Nichicon; TaMin_C: -55°C; ESR_ohm: 80m; Polarized: Y; SizeAreaWB_mm2: 159.9; U/M: EA; Value: 390uF; TaMax_C: 105°C; SizeZ_mm: 10.2; SizeX_mm: 11; SizeY_mm: 10.3; Cap_Case: 10x10; SizeArea_mm2: 113.3; CompType: Capacitor; Cap_F: 390µF; IRMS_A: 850mA; AEC Category: Q200
C65 C72 C75 C80 = CMP-0007136-5: CAP, CERM, 1 uF, 16 V, +/- 10%, X7R, AEC-Q200 Grade 1, 0603; Manufacturer: MuRata; TaMin_C: -55°C; Polarized: N; SizeAreaWB_mm2: 4.68; Value1: Unknown; U/M: EA; Value: 1uF; TaMax_C: 125°C; SizeZ_mm: 1; SizeX_mm: 1.6; SizeY_mm: 0.8; SizeArea_mm2: 1.28; AEC Qualified: Y; AEC Category: Q200
C66 C78 C91 C108 = CMP-0086249-1: CAP, CERM, 1 µF, 50 V,+/- 10%, X7R, AEC-Q200 Grade 1, 0805; Manufacturer: MuRata; Value: 1uF; AEC Qualified: Y; AEC Category: Q200; U/M: EA; AEC Grade: 1; SizeArea_mm2: 2.5; SizeAreaWB_mm2: 6.75; SizeZ_mm: 1.45; SizeX_mm: 2; Cap_Case: 0805; TaMax_C: 125°C; Polarized: N; SizeY_mm: 1.25; TaMin_C: -55°C
C67 C79 C93 C111 = CMP-2006-02379-2: Ceramic Capacitor for Automotive 150nF  ±10% 50VDC X7R 0603 Paper T/R
C68 C69 C81 C82 C94 C95 C112 C113 = CMP-0007174-4: CAP, CERM, 0.01 uF, 50 V, +/- 5%, C0G/NP0, 0603; Manufacturer: MuRata; TaMin_C: -55°C; Polarized: N; SizeAreaWB_mm2: 4.68; Value1: Unknown; U/M: EA; Value: 0.01uF; TaMax_C: 125°C; SizeZ_mm: 1; SizeX_mm: 1.6; SizeY_mm: 0.8; SizeArea_mm2: 1.28; Cap_F: 10nF; AEC Category: Q200
C70 C109 C110 = CMP-0064947-2: CAP, CERM, 1 uF, 6.3 V,+/- 10%, X7R, 0402; Manufacturer: MuRata; TaMin_C: -55°C; Polarized: N; SizeAreaWB_mm2: 3; Value1: Unknown; U/M: EA; Value: 1uF; TaMax_C: 125°C; SizeZ_mm: 0.6; SizeX_mm: 1; SizeY_mm: 0.5; Cap_F: 1µF; AEC Category: Q200
C71 = CMP-0006623-2: CAP, CERM, 0.1 uF, 6.3 V, +/- 10%, X7R, 0402; Manufacturer: MuRata; TaMin_C: -55°C; Polarized: N; SizeAreaWB_mm2: 3; Value1: Unknown; U/M: EA; Value: 0.1uF; TaMax_C: 125°C; SizeZ_mm: 0.6; SizeX_mm: 1; SizeY_mm: 0.5; Cap_F: 100nF; AEC Category: Q200
C73 C83 C104 C114 = CMP-0006687-2: CAP, CERM, 330 pF, 50 V, +/- 10%, X7R, 0402; Manufacturer: MuRata; TaMin_C: -55°C; Polarized: N; SizeAreaWB_mm2: 3; Value1: Unknown; U/M: EA; Value: 330pF; TaMax_C: 125°C; SizeZ_mm: 0.6; SizeX_mm: 1; SizeY_mm: 0.5; Value2: 50V; AEC Category: Q200
C74 C76 = CMP-0007137-5: CAP, CERM, 1 uF, 16 V, +/- 20%, X7R, AEC-Q200 Grade 1, 0603; Manufacturer: MuRata; TaMin_C: -55°C; Polarized: N; SizeAreaWB_mm2: 4.68; Value1: Unknown; U/M: EA; Value: 1uF; TaMax_C: 125°C; SizeZ_mm: 1; SizeX_mm: 1.6; SizeY_mm: 0.8; SizeArea_mm2: 1.28; AEC Qualified: Y; AEC Category: Q200
C77 = CMP-0007121-4: CAP, CERM, 2.2 uF, 16 V, +/- 10%, X7R, 0603; Manufacturer: Taiyo Yuden; TaMin_C: -55°C; Polarized: N; SizeAreaWB_mm2: 4.68; Value1: Unknown; U/M: EA; Value: 2.2uF; TaMax_C: 125°C; SizeZ_mm: 1; SizeX_mm: 1.6; SizeY_mm: 0.8; SizeArea_mm2: 1.28; AEC Category: Q200
C84 C85 C87 C88 C106 C107 = CMP-06035-059042-1: Multilayer Ceramic Capacitors MLCC - SMD/SMT 0805 1uF 20%, 50VDC,  X7R 15%
C92 = CMP-0006351-2: CAP, CERM, 0.1 uF, 16 V, +/- 10%, X7R, 0402; Manufacturer: MuRata; TaMin_C: -55°C; Polarized: N; SizeAreaWB_mm2: 3; Value1: Unknown; U/M: EA; Value: 0.1uF; TaMax_C: 125°C; SizeZ_mm: 0.6; SizeX_mm: 1; SizeY_mm: 0.5; Cap_F: 100nF; AEC Category: Q200
C96-C103 = CMP-2006-02223-2: Cap Ceramic 0.1uF 50V X7R 10% Pad SMD 0603 Soft Termination +125°C Automotive T/R
C105 = CMP-0007393-4: CAP, CERM, 0.33 uF, 16 V, +/- 10%, X7R, 0603; Manufacturer: MuRata; TaMin_C: -55°C; Polarized: N; SizeAreaWB_mm2: 4.68; Value1: Unknown; U/M: EA; Value: 0.33uF; TaMax_C: 125°C; SizeZ_mm: 1; SizeX_mm: 1.6; SizeY_mm: 0.8; SizeArea_mm2: 1.28; AEC Category: Q200
C116 = CMP-0006237-2: CAP, CERM, 0.1 uF, 16 V, +/- 10%, X7R, AEC-Q200 Grade 1, 0402; Manufacturer: Kemet; TaMin_C: -55°C; Polarized: N; SizeAreaWB_mm2: 3; Value1: Unknown; U/M: EA; Value: 0.1uF; TaMax_C: 125°C; SizeZ_mm: 0.6; SizeX_mm: 1; SizeY_mm: 0.5; AEC Qualified: Y; Cap_F: 100nF; AEC Category: Q200
D8 D10 = CMP-0002890-1: LED, Orange, SMD; Manufacturer: Lite-On; PartNumber: LTST-C170KFKT; Io_A: 20mA; Value1: W; U/M: EA; Vf_V: 2V; Type: AlInGaP
D9 = CMP-0002829-3: LED, Red, SMD; Manufacturer: Lite-On; PartNumber: LTST-C170KRKT; SizeZ_mm: 1.2; Value1: W; SizeY_mm: 1.25; Value2: 2V; SizeArea_mm2: 2.5; SizeX_mm: 2; SizeAreaWB_mm2: 6.75; Io_A: 20mA; Type: AlInGaP
H2 = CMP-0123147-2: 20.0 x 41.4 x 32.8 mm  BGA Heat Sink - High Performance Device Specific - TI; Manufacturer: Advanced Thermal Solutions; AEC Qualified: No; SizeZ_mm: 32.77mm; Thermal Resistance Forced Air Flow: 4.6°C/W
J17 = CMP-0055127-1: as J13 on sheet PROC191_Power
J18 J20 J22 J24 = CMP-0055128-1: as J15 on sheet PROC191_Power
J19 J21 J23 = CMP-0055127-1: Binding Post, RED, TH; Manufacturer: Keystone; CNHeader: FALSE; Green_Lifecycle: Active; Green_REACh: Passed; CompType: Connector
J25 = CMP-0055322-1: Header, 2.54 mm, 3x1, Tin, TH; CNHeader: TRUE; Green_Lifecycle: Active; Shrouded: N; Gender: Male; Green_REACh: Passed; Row_Count: 1; Pitch_mm: 2.54; CT: FALSE
L6-L9 = CMP-0059924-1: Inductor, 3.3 uH, 4.5 A, 0.038 ohm, AEC-Q200 Grade 0, SMD; Manufacturer: Cyntec; Isat: 4.5A @ 30% inductance drop; Irms: 5A @ 40C rise; SizeAreaWB_mm2: 54.0125; DCR_ohm: 0.038; Value: 3.3uH; Imax_A: 4.5A; SizeZ_mm: 3; SizeX_mm: 5.45; SizeY_mm: 5.25; SizeArea_mm2: 28.6125; Ind_H: 3.3µH; AEC Qualified: Y; AEC Grade: 0; AEC Category: Q200
Q9-Q11 = CMP-0000010-3: MOSFET, P-CH, -20 V, -0.39 A, SOT-323; Alternate Manufacturer: None; Manufacturer: Infineon Technologies; Value: -20V; Rdson45_ohm: 1.2; SizeX_mm: 2.2; AEC Category: Q101; ChMode: Enhancement; Vgs_V: -12V; Value1: 1; IdsMax_A: -390mA; ChType: P; SizeAreaWB_mm2: 10.24; QgTyp_nC: -0.5; SizeArea_mm2: 4.84; SizeZ_mm: 1.1
R35 = CMP-0022752-4: RES, 110 k, 1%, 0.1 W, 0603; Manufacturer: Yageo; Power_W: 100mW; TempCo: 100 ppm/C; Value: 110k; EIA_Code: E96; SizeX_mm: 1.6; SizeY_mm: 0.8; SizeZ_mm: 1; Value2: 0.1W; SizeArea_mm2: 1.28; AEC Qualified: N; VDC_V: 75V; AEC Category: Q200; SizeAreaWB_mm2: 4.68
R58 R60 R63 R66 R72 R77 = CMP-0026680-1: RES, 220, 1%, 0.1 W, AEC-Q200 Grade 0, 0402; Manufacturer: Panasonic; Power_W: 100mW; TempCo: 100 ppm/C; Value_Code: 220R; U/M: EA; Value: 220; SizeX_mm: 1; SizeY_mm: 0.5; SizeZ_mm: 0.6; Value2: 0.1W; AEC Qualified: Y; VDC_V: 50V; AEC Grade: 0; AEC Category: Q200
R67-R70 = CMP-0026753-1: RES, 100 k, 1%, 0.063 W, AEC-Q200 Grade 0, 0402; Manufacturer: Stackpole Electronics Inc; Power_W: 63mW; TempCo: 100 ppm/C; U/M: EA; Value: 100k; EIA_Code: E96; SizeX_mm: 1; SizeY_mm: 0.5; SizeZ_mm: 0.6; Value2: 0.063W; AEC Qualified: Y; VDC_V: 50V; AEC Grade: 0; AEC Category: Q200
R71 R76 R79 R81 = CMP-0025805-4: RES, 3.3, 5%, 0.1 W, AEC-Q200 Grade 0, 0603; Manufacturer: Vishay-Dale; Power_W: 100mW; TempCo: 200 ppm/C; Value_Code: 3R30; Value: 3.3; EIA_Code: E24; SizeX_mm: 1.6; SizeY_mm: 0.8; SizeZ_mm: 1; Value2: 0.1W; SizeArea_mm2: 1.28; AEC Qualified: Y; VDC_V: 75V; AEC Category: Q200; AEC Grade: 0
R73 R75 = CMP-0089144-1: 1 kOhms ±5% 0.1W, 1/10W Chip Resistor 0603 (1608 Metric) Automotive AEC-Q200 Thick Film; Manufacturer: Panasonic; Power_W: 100mW; AEC Qualified: Yes; Voltage: 75V; AEC Grade: Grade 0; SizeZ_mm: 0.55mm; TempCo: 200ppm/°C
R74 R86 R95 = CMP-0089143-1: as R49 on sheet PROC191_Power
R78 = CMP-0026997-2: as R1 on sheet PROC191_ExpansionConnector
R88 R89 R93 = CMP-0078212-1: as R27 on sheet PROC191_Power
R90 = CMP-0026754-1: RES, 10.0 k, 1%, 0.063 W, AEC-Q200 Grade 0, 0402; Manufacturer: Stackpole Electronics Inc; Power_W: 63mW; TempCo: 100 ppm/C; Value_Code: 10k0; U/M: EA; Value: 10.0k; EIA_Code: E96; Res_ohm: 10k; SizeX_mm: 1; SizeY_mm: 0.5; SizeZ_mm: 0.6; Value2: 0.063W; CompType: Resistor; AEC Qualified: Y; VDC_V: 50V; AEC Grade: 0; AEC Category: Q200
R94 = CMP-0022746-5: as R52 on sheet PROC191_Power
SW4 = CMP-0120665-1: DIP Switch, 1 POS, SPST, Raised, 6VDC, 100mA, CFS Series; Manufacturer: Nidec Components Corporation; PositionCount: 1; SizeZ_mm: 5.3mm; VDC_V: 6V; AEC Qualified: No; Coil Resistance_ohm: 50mΩ; Electromechanical Life: 1000Cycles; Standoff Height: 0.1mm
TP17-TP19 TP23-TP32 = CMP-0003825-1: 1mm Test Point, SMT; Manufacturer: Any
U7 = CMP-0096441-1: 26.4 V, 7.5 A Digital Input 4-Channel Automotive Class-D Audio Amplifier with Current Sense and Real-time Load Diagnostics; Manufacturer: Texas Instruments; Part Number: TAS6554QDKQRQ1; Power At Speaker R: 50W @ 2Ω; Max Supply Voltage: 26.4V; TaMax_C: +125°C; SizeZ_mm: 2.475mm; Min Supply Voltage: 4.5V; AEC Qualified: Yes; AEC Grade: Grade 1; TaMin_C: -40°C; Standoff Height: 0mm; Number Of Channels: 4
